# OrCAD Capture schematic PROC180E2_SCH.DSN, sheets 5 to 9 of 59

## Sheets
5 43. AUDIO MICROPHONE_LINE IN 2: size C; title: AUDIO - MICROPHONE/LINE IN 2
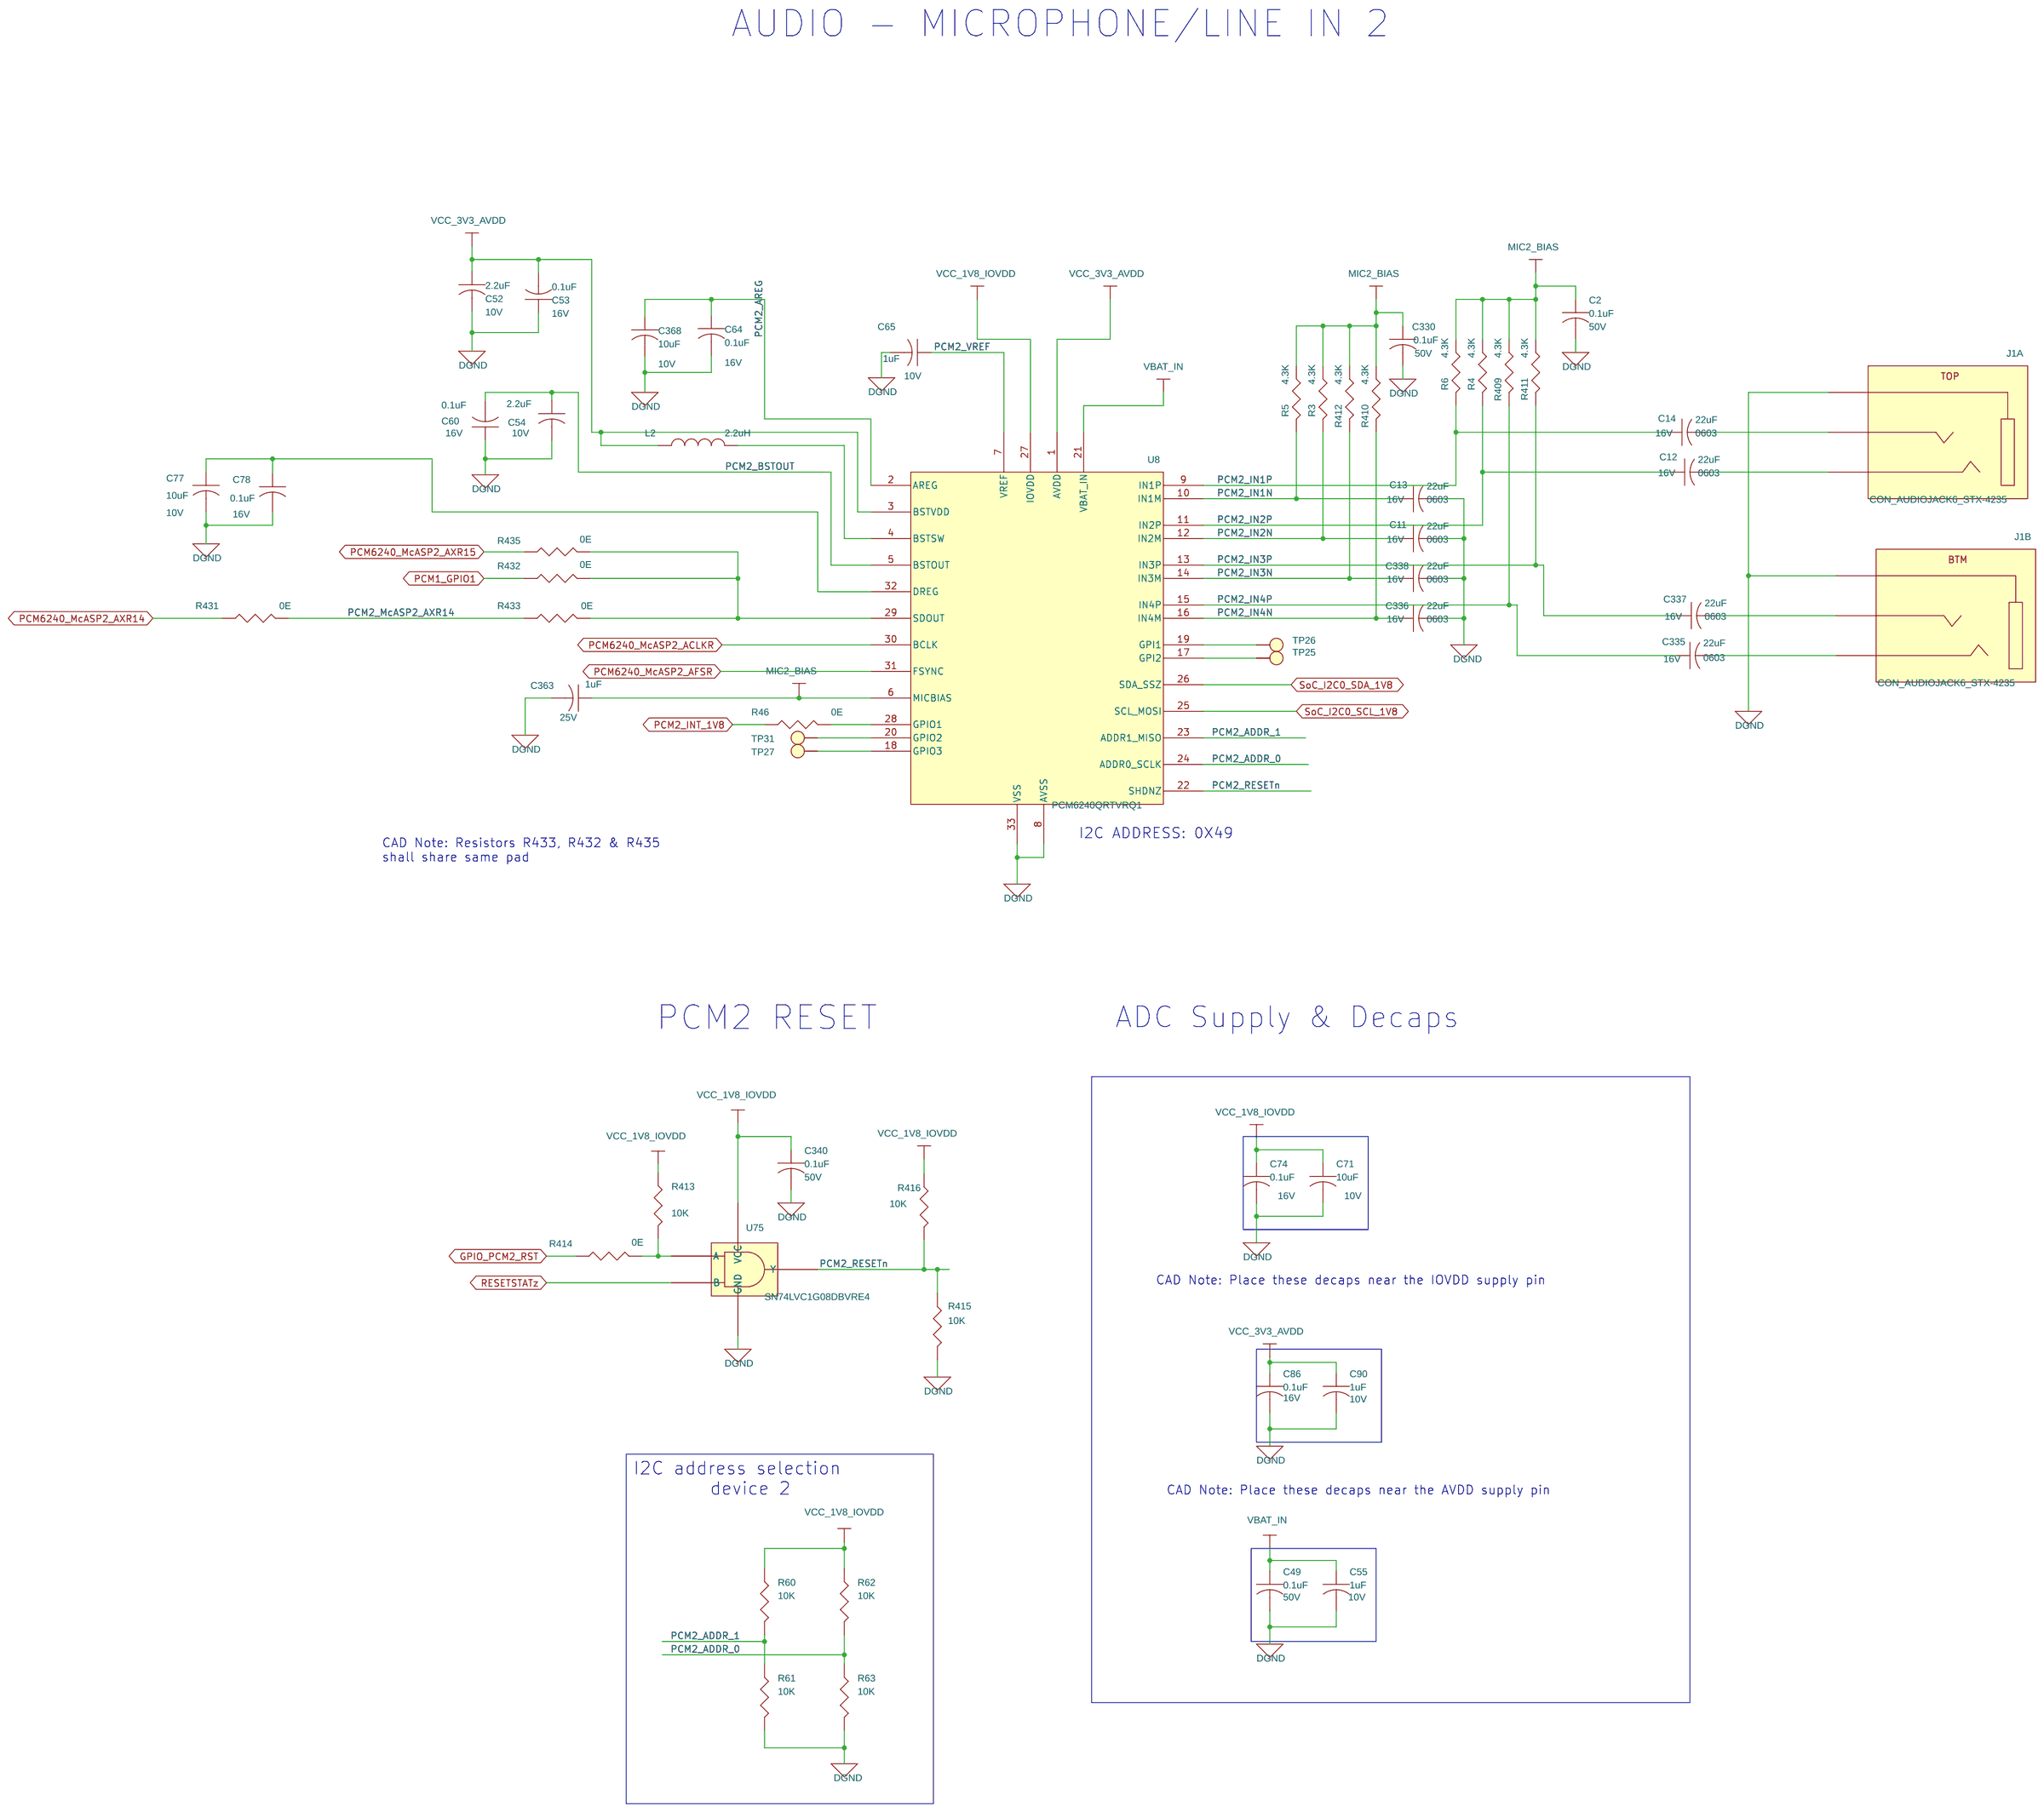
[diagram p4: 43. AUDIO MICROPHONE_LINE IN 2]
6 46. AUDIO EXPANSION 2: size C; title: AUDIO EXPANSION  CONNECTOR  #2
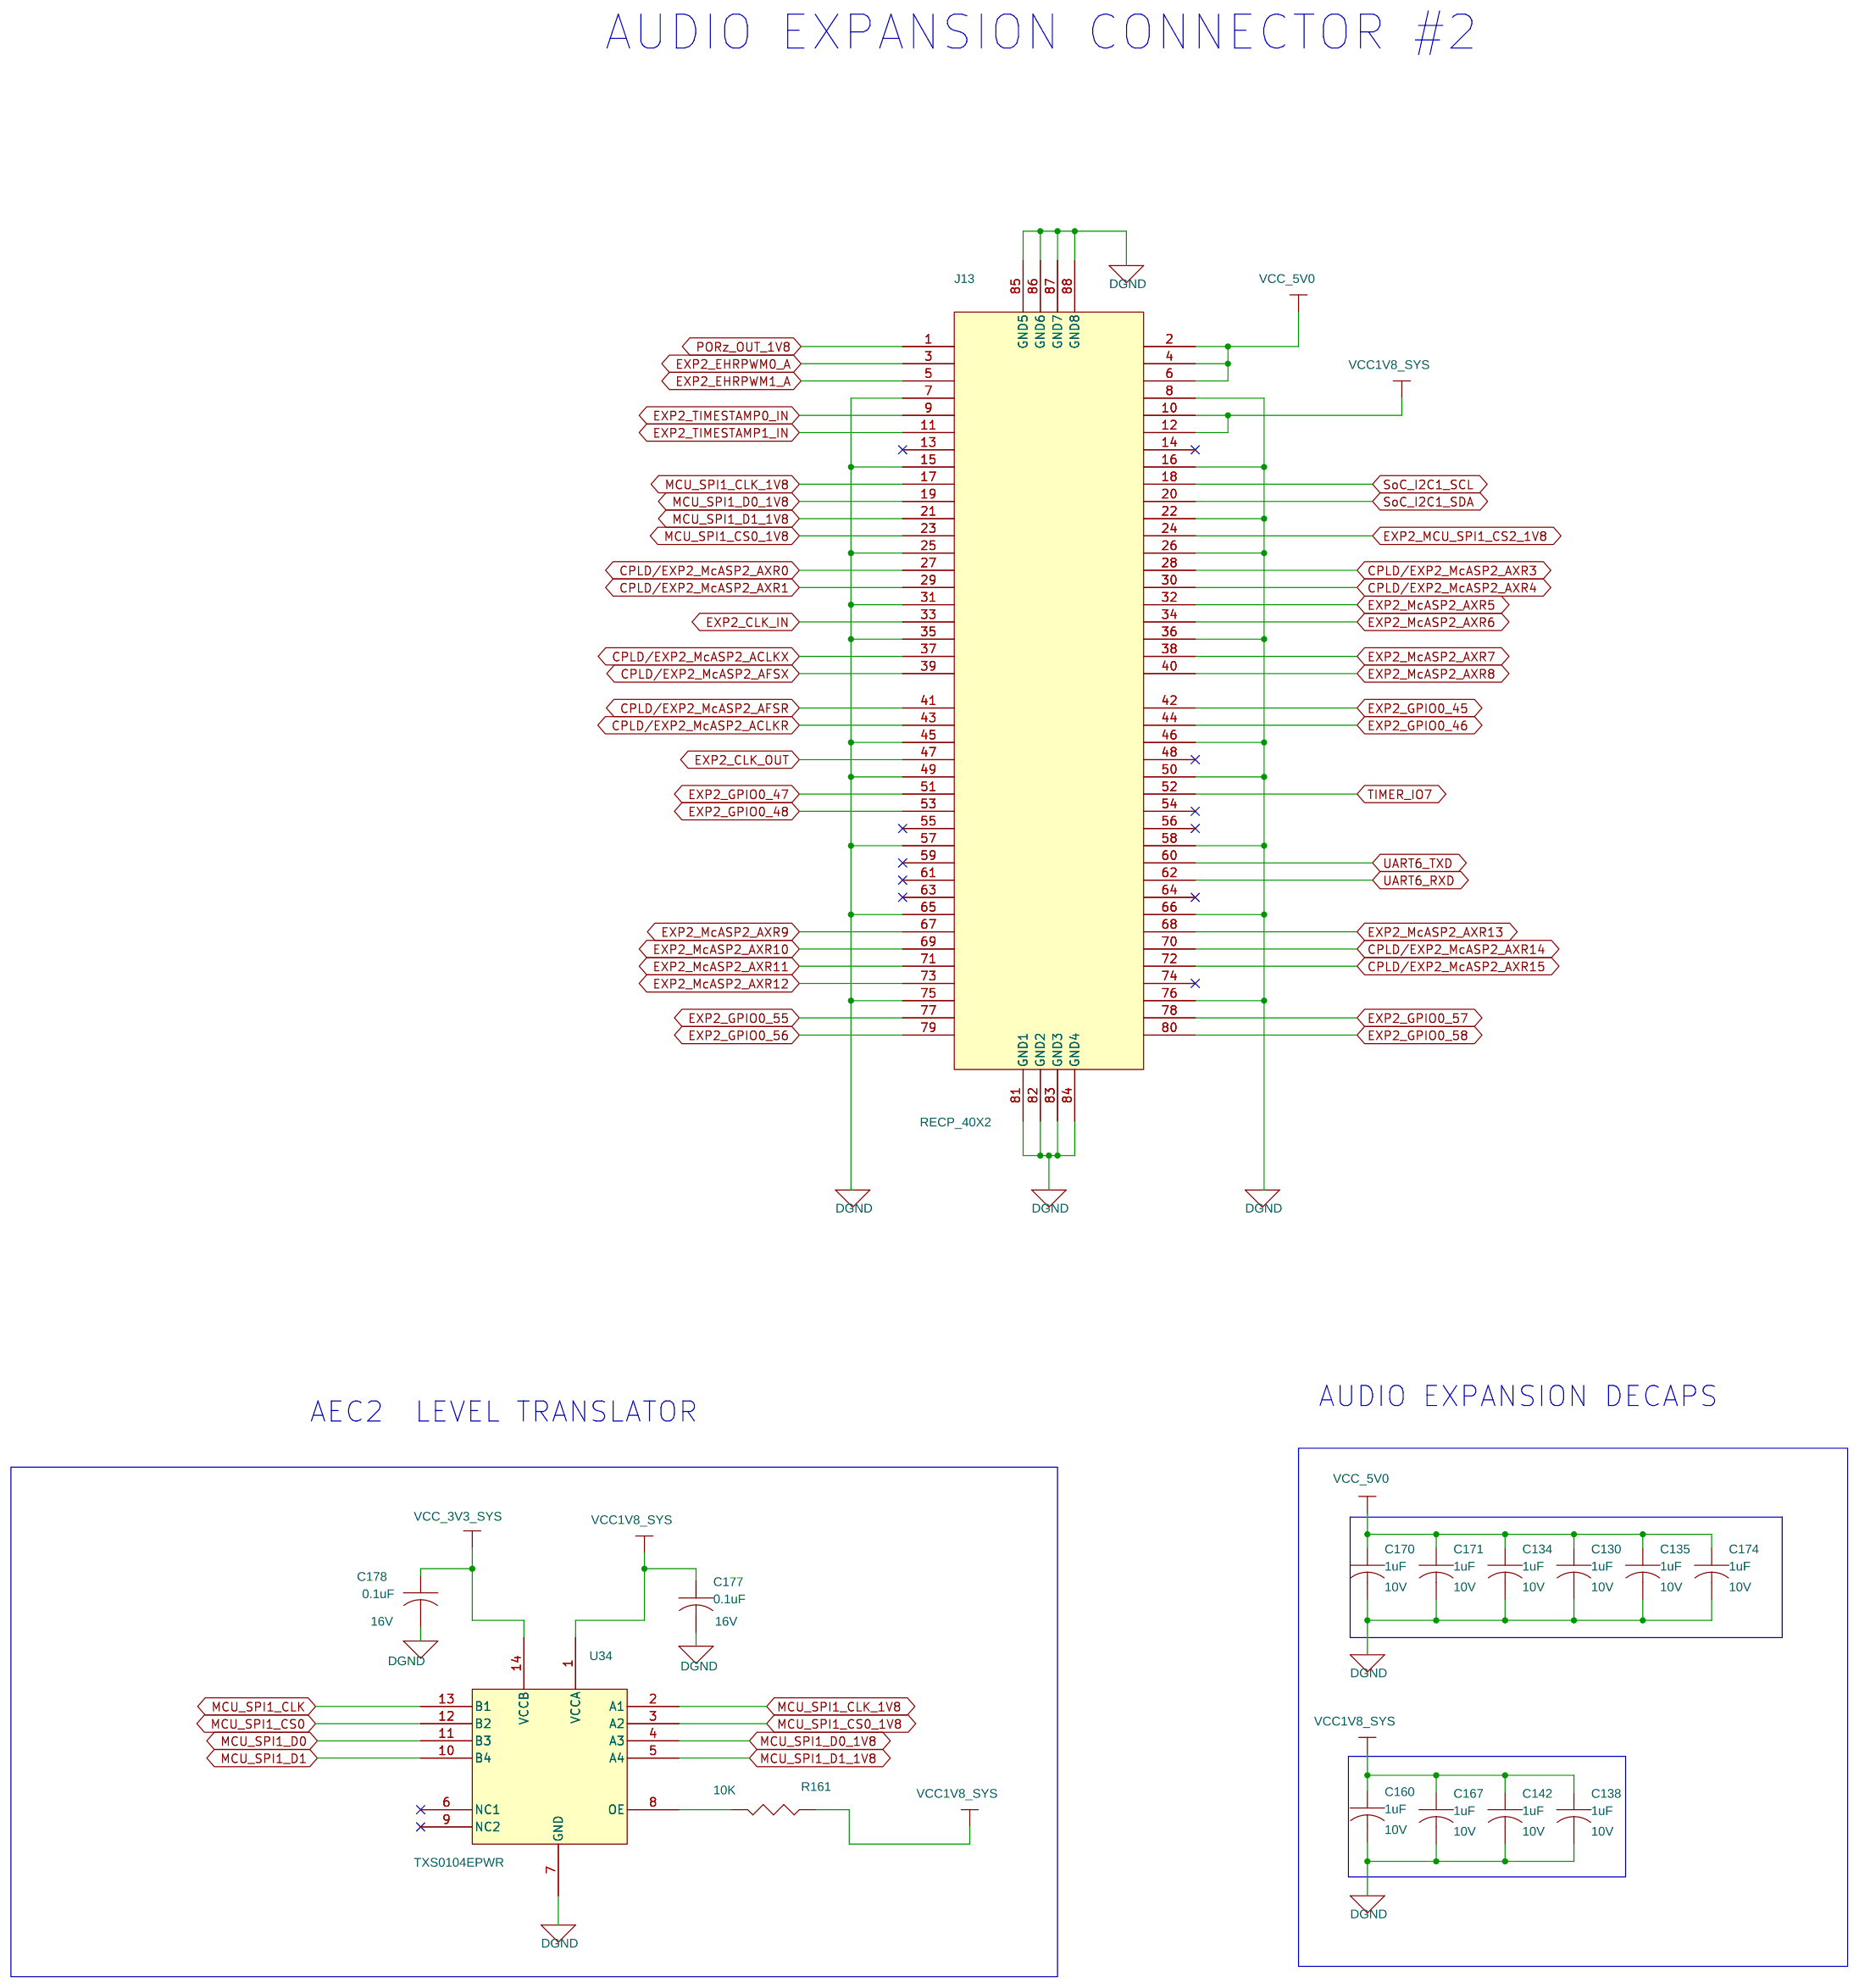
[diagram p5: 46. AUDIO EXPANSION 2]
7 30. SOC PERIPHERALS 3: size C; title: SOC PERIPHERALS 3
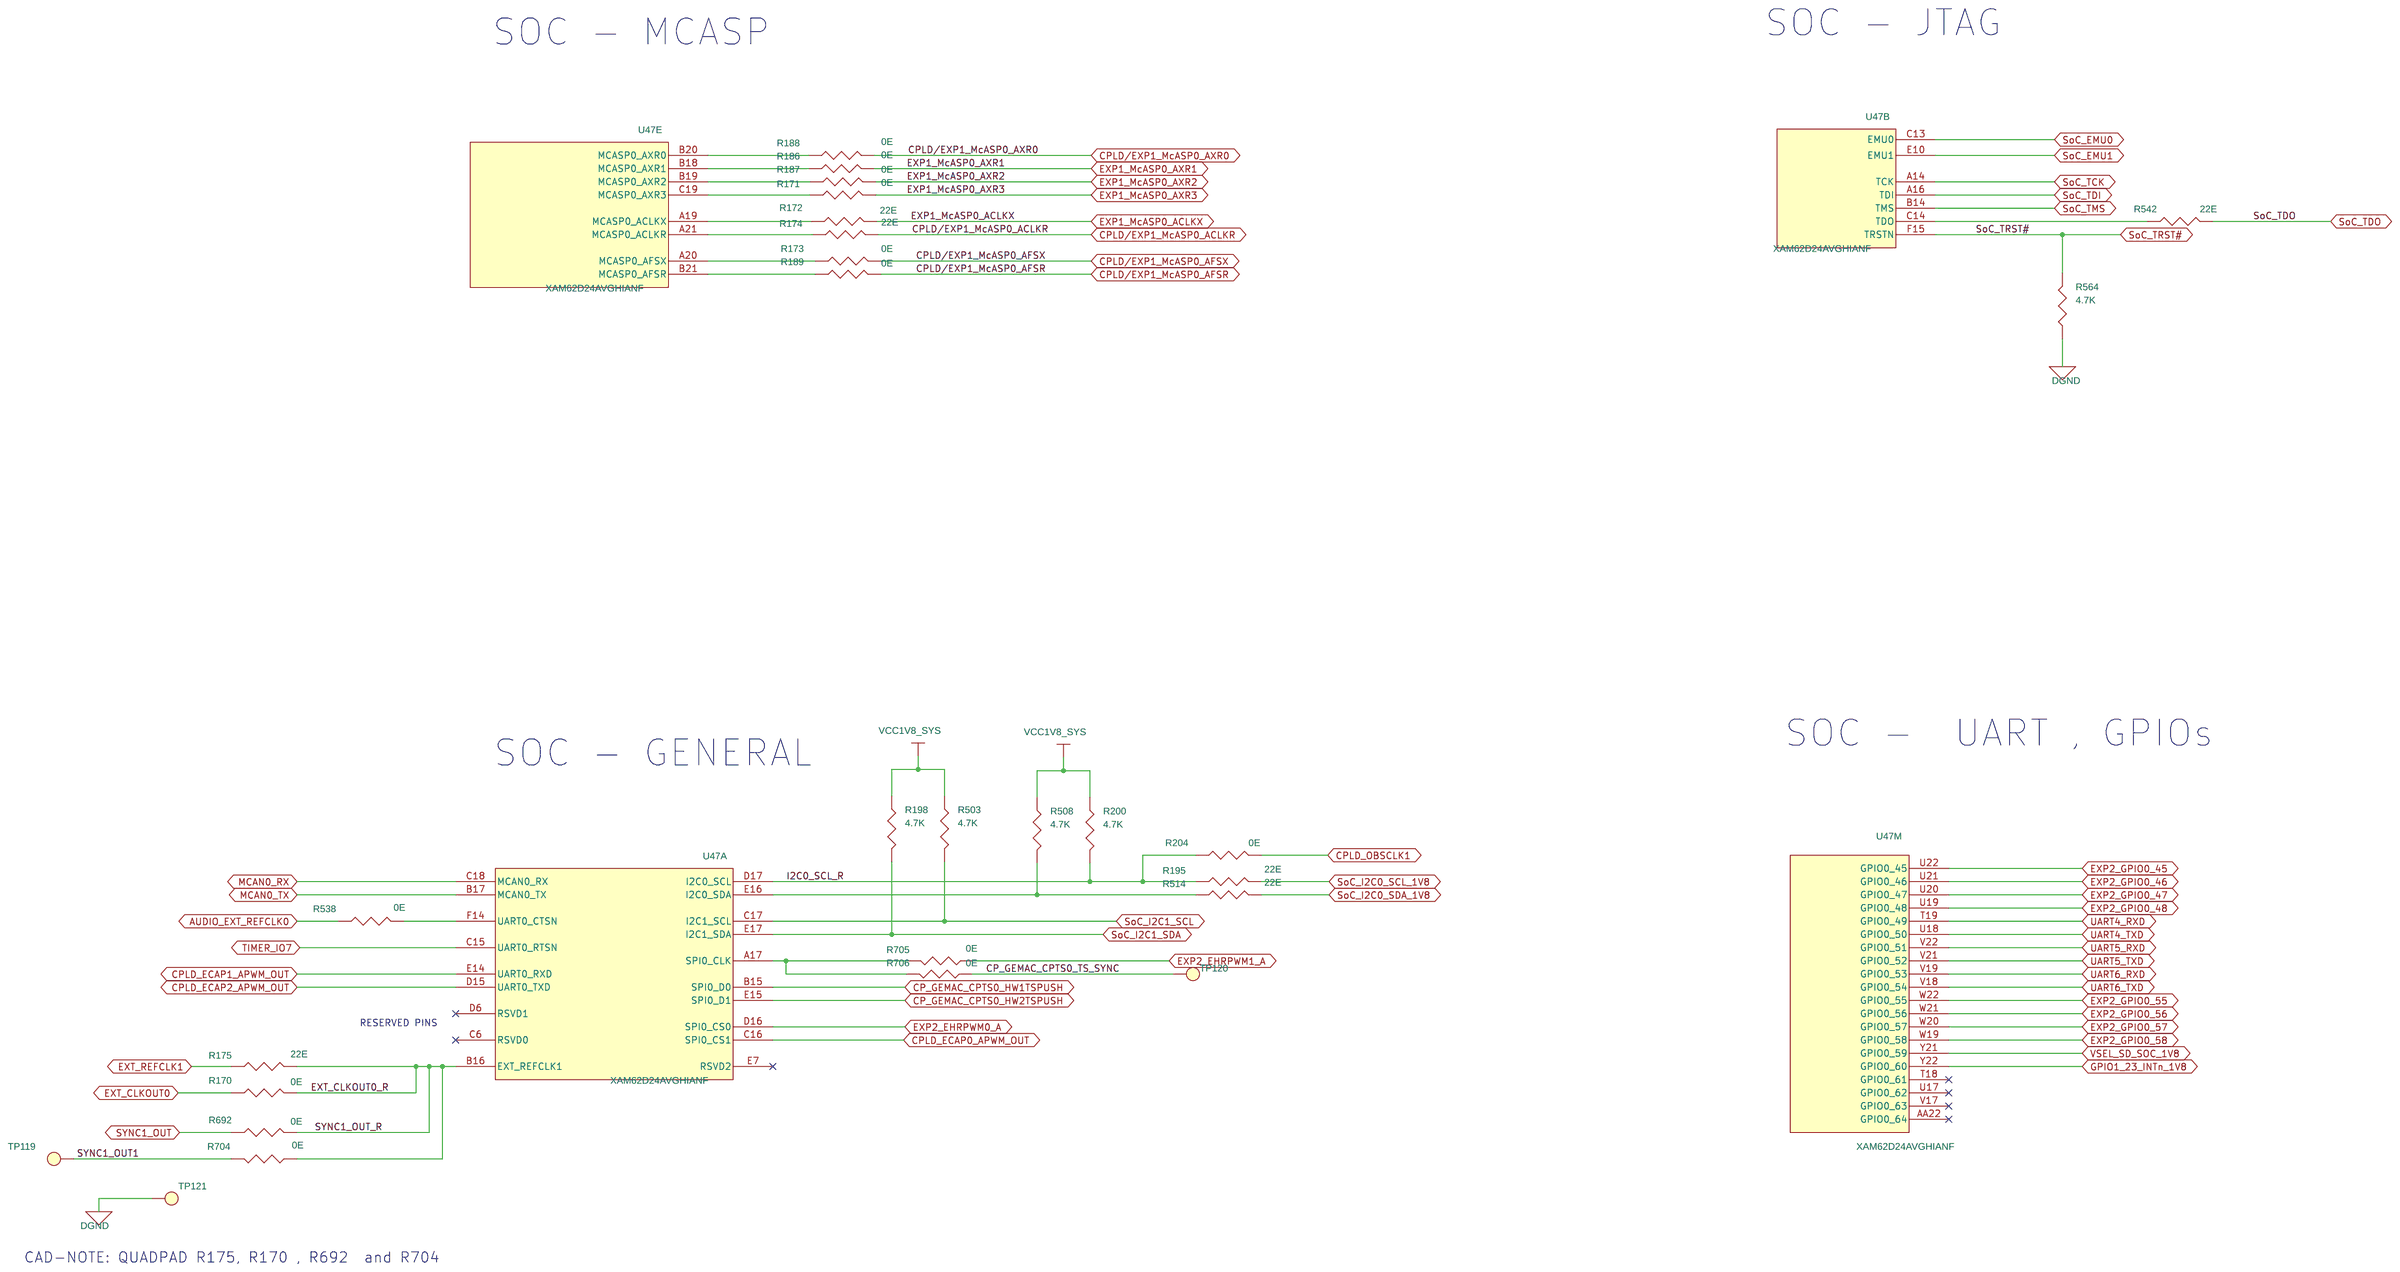
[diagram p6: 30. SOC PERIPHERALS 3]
8 29. SOC PERIPHERALS 2: size C; title: SOC PERIPHERALS  2
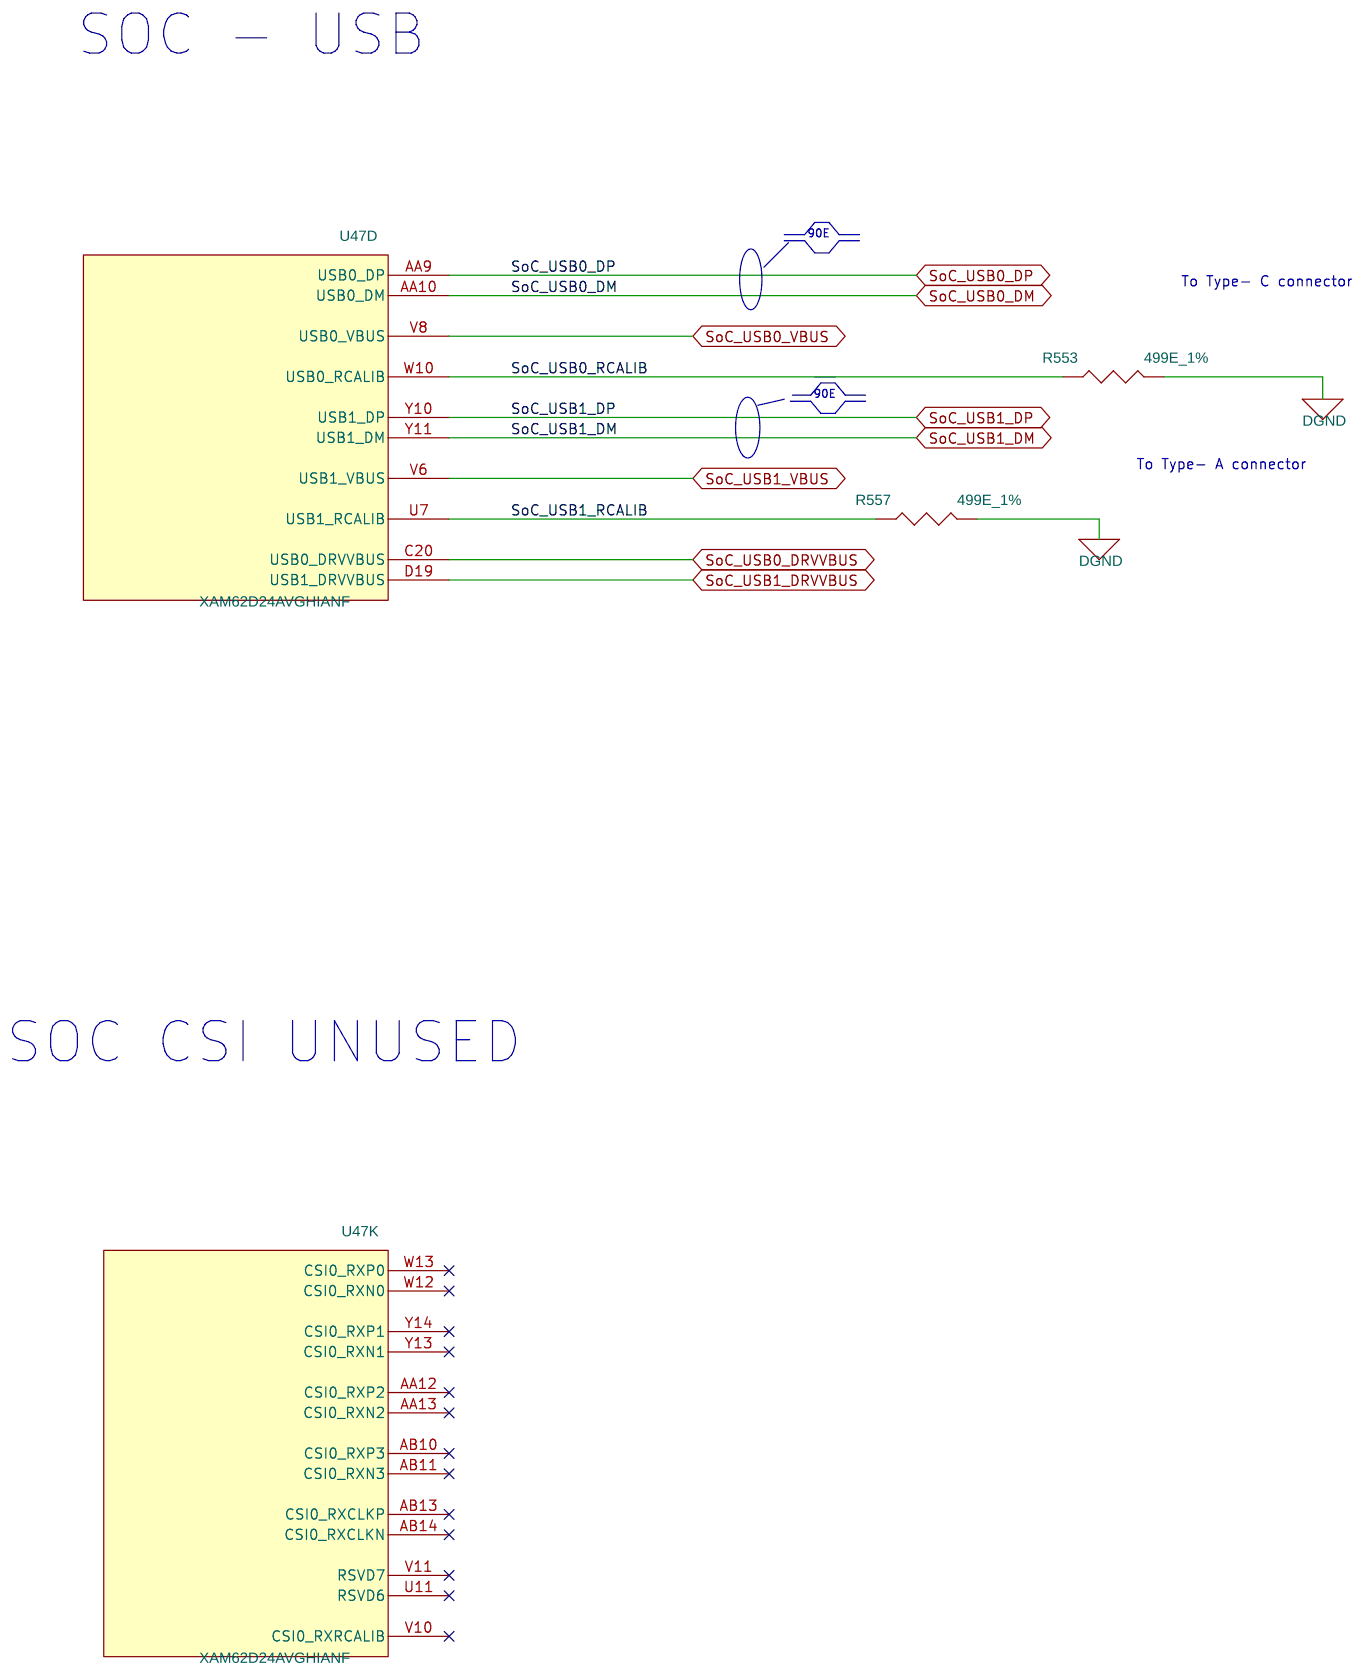
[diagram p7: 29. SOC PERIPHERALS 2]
9 23. BOOT MODE SWITCHES: size C; title: BOOT MODE SWITCHES
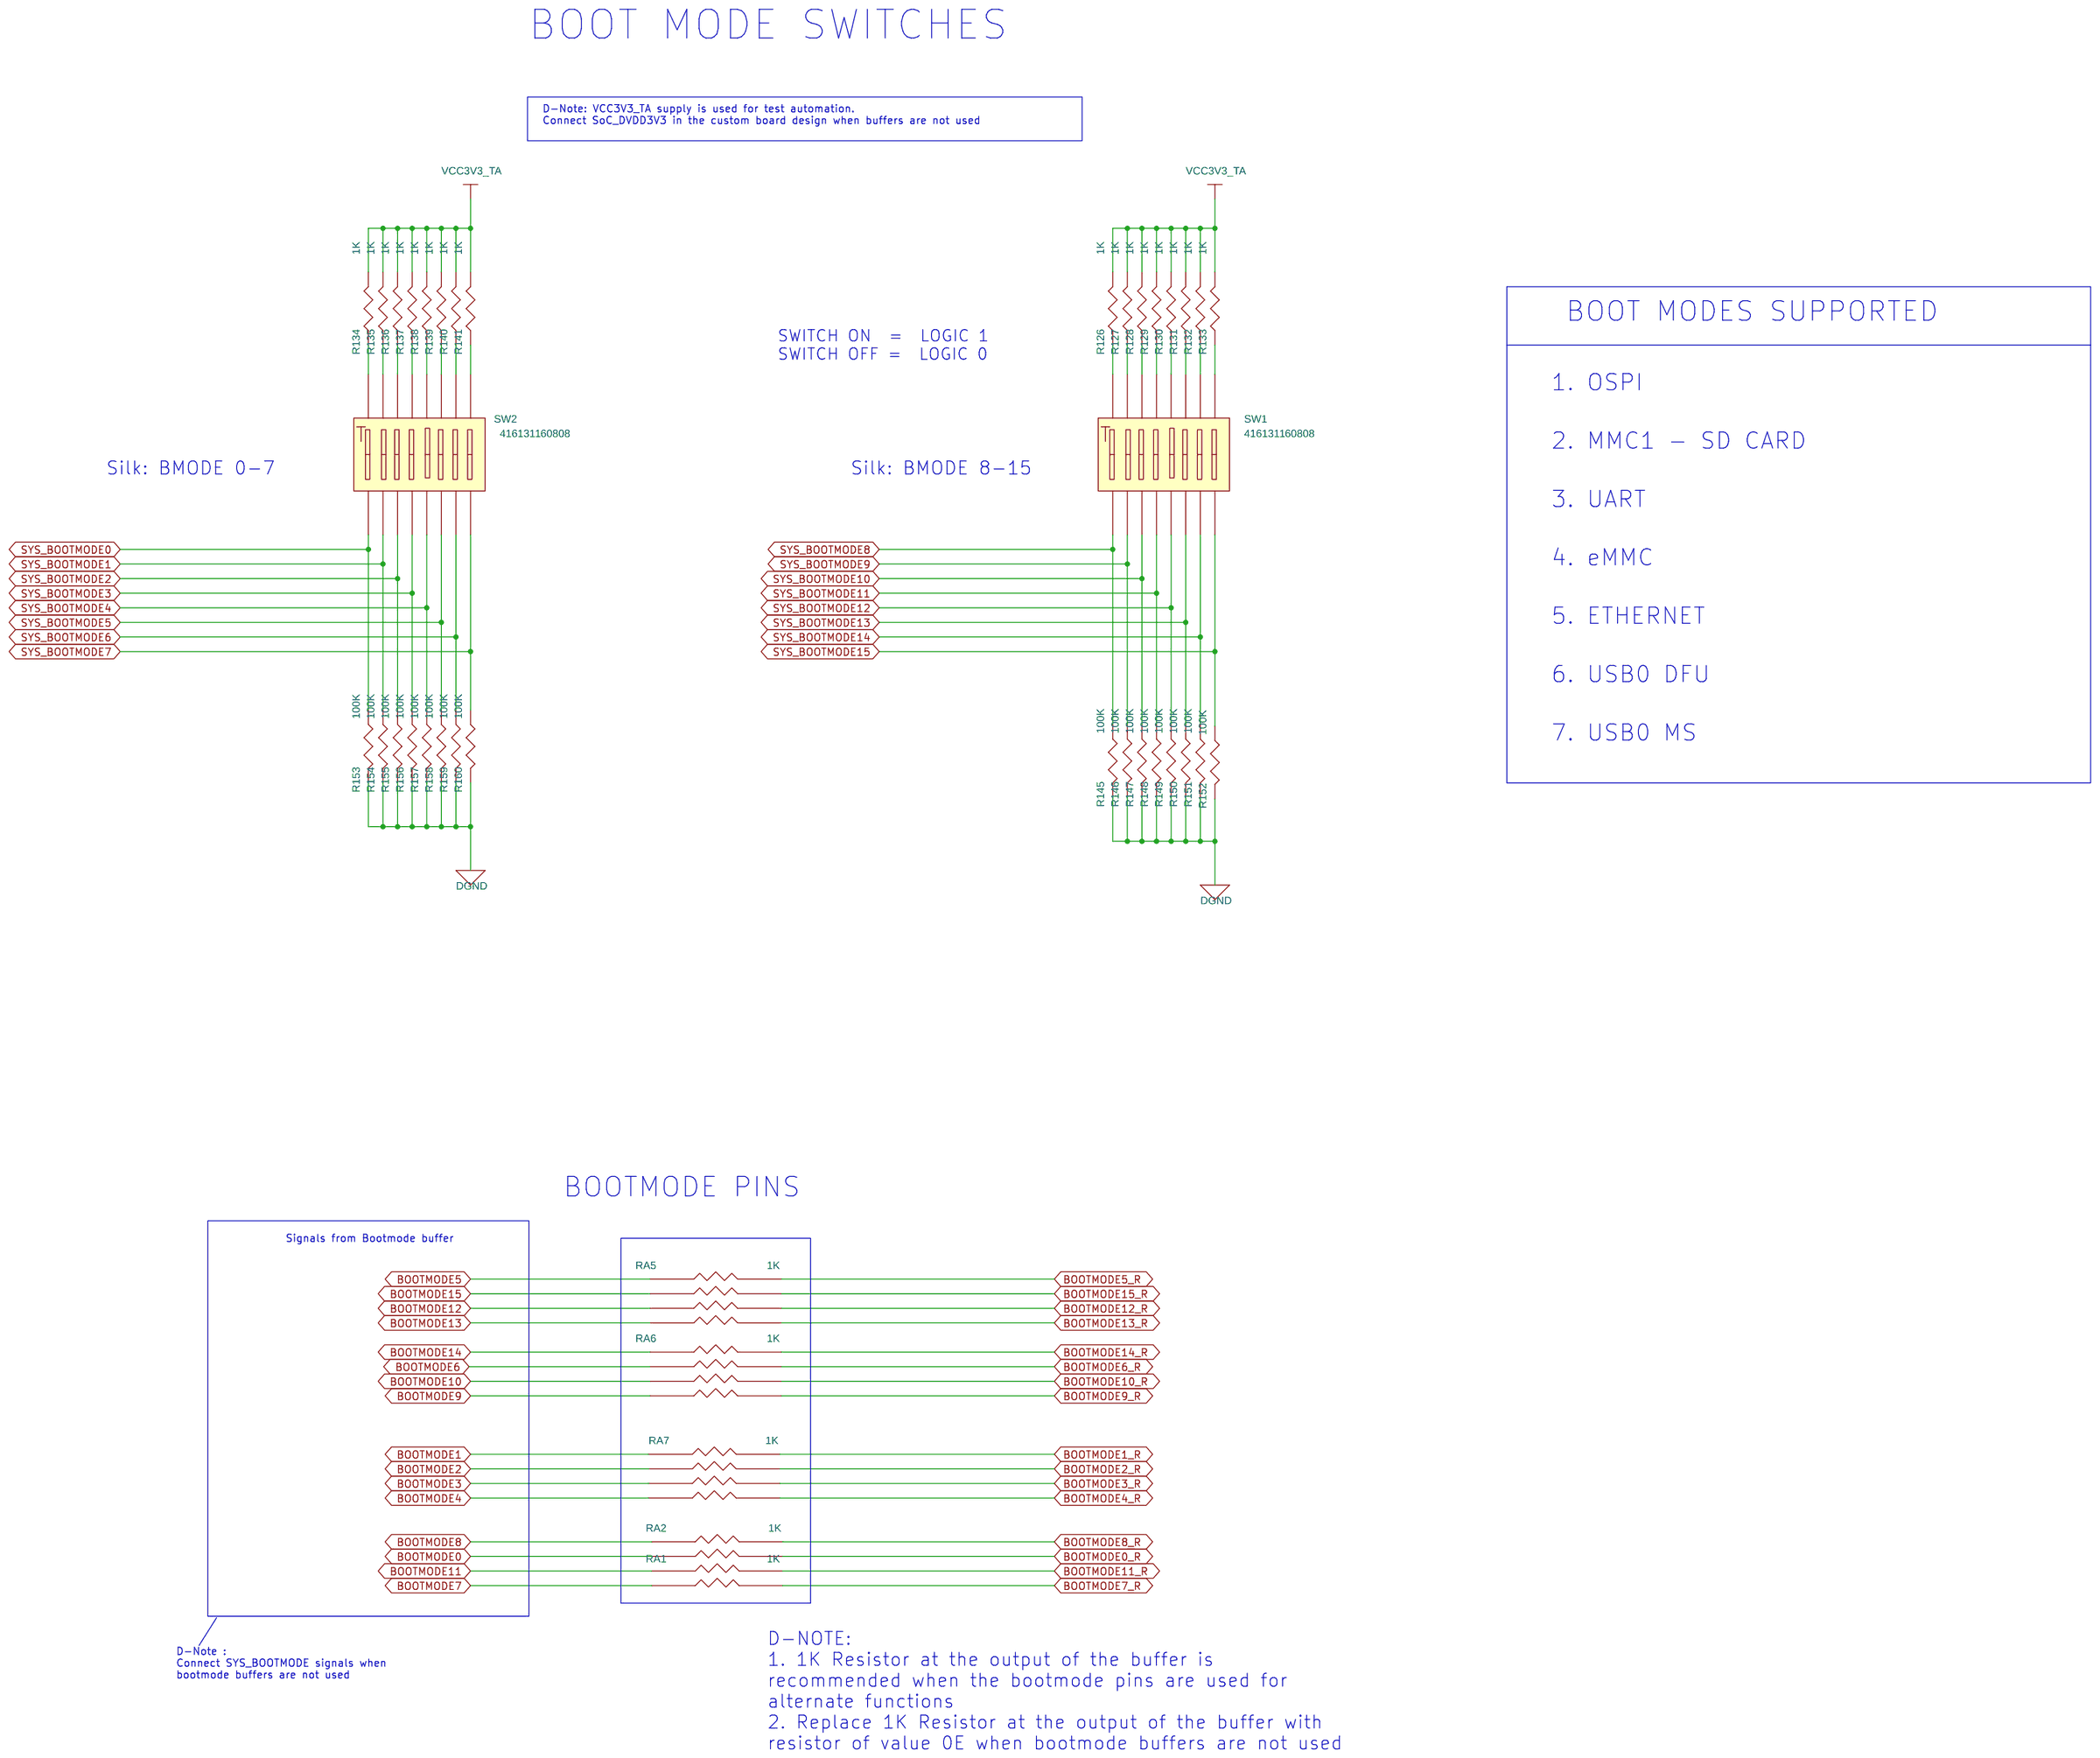
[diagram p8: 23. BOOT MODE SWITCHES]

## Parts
sheet 21. SOC RESET - 1
U47  XAM62D24AVGHIANF  [FBGA484_31-49_710X710_2-7]  (sections A,B,C,D,E,F,G,H,I,J,K,L,M,N,O,P,Q)
sheet 23. BOOT MODE SWITCHES
R126  1K  [RES0201_0-5]
R127  1K  [RES0201_0-5]
R128  1K  [RES0201_0-5]
R129  1K  [RES0201_0-5]
R130  1K  [RES0201_0-5]
R131  1K  [RES0201_0-5]
R132  1K  [RES0201_0-5]
R133  1K  [RES0201_0-5]
R134  1K  [RES0201_0-5]
R135  1K  [RES0201_0-5]
R136  1K  [RES0201_0-5]
R137  1K  [RES0201_0-5]
R138  1K  [RES0201_0-5]
R139  1K  [RES0201_0-5]
R140  1K  [RES0201_0-5]
R141  1K  [RES0201_0-5]
R145  100K  [RES0201_0-5]
R146  100K  [RES0201_0-5]
R147  100K  [RES0201_0-5]
R148  100K  [RES0201_0-5]
R149  100K  [RES0201_0-5]
R150  100K  [RES0201_0-5]
R151  100K  [RES0201_0-5]
R152  100K  [RES0201_0-5]
R153  100K  [RES0201_0-5]
R154  100K  [RES0201_0-5]
R155  100K  [RES0201_0-5]
R156  100K  [RES0201_0-5]
R157  100K  [RES0201_0-5]
R158  100K  [RES0201_0-5]
R159  100K  [RES0201_0-5]
R160  100K  [RES0201_0-5]
RA1  1K  [RESA_EXB_0201-2_0-5]
RA2  1K  [RESA_EXB_0201-2_0-5]
RA5  1K  [RESA_EXB_0201-4_0-5]
RA6  1K  [RESA_EXB_0201-4_0-5]
RA7  1K  [RESA_EXB_0201-4_0-5]
SW1  416131160808  [SW16_416131160808_460X230_SMD_2-7]
SW2  416131160808  [SW16_416131160808_460X230_SMD_2-7]
sheet 29. SOC PERIPHERALS 2
R553  499E_1%  [RES0402_0-5]
R557  499E_1%  [RES0402_0-5]
sheet 30. SOC PERIPHERALS 3
R170  0E  [RES0201_0-5]
R171  0E  [RES0402_0-5]
R172  22E  [RES0402_0-5]
R173  0E  [RES0402_0-5]
R174  22E  [RES0402_0-5]
R175  22E  [RES0201_0-5]
R186  0E  [RES0402_0-5]
R187  0E  [RES0402_0-5]
R188  0E  [RES0402_0-5]
R189  0E  [RES0402_0-5]
R195  22E  [RES0402_0-5]
R198  4.7K  [RES0201_0-5]
R200  4.7K  [RES0201_0-5]
R204  0E  [RES0201_0-5]
R503  4.7K  [RES0201_0-5]
R508  4.7K  [RES0201_0-5]
R514  22E  [RES0402_0-5]
R538  0E  [RES0201_0-5]
R542  22E  [RES0201_0-5]
R564  4.7K  [RES0201_0-5]
R692  0E  [RES0201_0-5]
R704  0E  [RES0201_0-5]
R705  0E  [RES0201_0-5]
R706  0E  [RES0201_0-5]
TP119  THRU HOLE  [TP_40X65]
TP120  THRU HOLE  [TP_40X65]
TP121  THRU HOLE  [TP_40X65]
sheet 43. AUDIO MICROPHONE_LINE IN 2
C2  0.1uF  [CAP0402_0-75]
C11  22uF  [CAP0603_1]
C12  22uF  [CAP0603_1]
C13  22uF  [CAP0603_1]
C14  22uF  [CAP0603_1]
C49  0.1uF  [CAP0402_0-75]
C52  2.2uF  [CAP0201_0-75]
C53  0.1uF  [CAP0201_0-5]
C54  2.2uF  [CAP0201_0-75]
C55  1uF  [CAP0201_0-5]
C60  0.1uF  [CAP0201_0-5]
C64  0.1uF  [CAP0201_0-5]
C65  1uF  [CAP0201_0-5]
C71  10uF  [CAP0402_0-75]
C74  0.1uF  [CAP0201_0-5]
C77  10uF  [CAP0402_0-75]
C78  0.1uF  [CAP0201_0-5]
C86  0.1uF  [CAP0201_0-5]
C90  1uF  [CAP0201_0-5]
C330  0.1uF  [CAP0402_0-75]
C335  22uF  [CAP0603_1]
C336  22uF  [CAP0603_1]
C337  22uF  [CAP0603_1]
C338  22uF  [CAP0603_1]
C340  0.1uF  [CAP0402_0-75]
C363  1uF  [CAP0805_1-5]
C368  10uF  [CAP0402_0-75]
J1  CON_AUDIOJACK6_STX-4235  [CON_AV6_STX-4235-3-3_S_R_T_26]  (sections A,B)
L2  2.2uH  [IND0806]
R3  4.3K  [RES0402_0-5]
R4  4.3K  [RES0402_0-5]
R5  4.3K  [RES0402_0-5]
R6  4.3K  [RES0402_0-5]
R46  0E  [RES0201_0-5]
R60  10K  [RES0201_0-5]
R61  10K  [RES0201_0-5]
R62  10K  [RES0201_0-5]
R63  10K  [RES0201_0-5]
R409  4.3K  [RES0402_0-5]
R410  4.3K  [RES0402_0-5]
R411  4.3K  [RES0402_0-5]
R412  4.3K  [RES0402_0-5]
R413  10K  [RES0402_0-5]
R414  0E  [RES0201_0-5]
R415  10K  [RES0402_0-5]
R416  10K  [RES0402_0-5]
R431  0E  [RES0201_0-5]
R432  0E  [RES0201_0-5]
R433  0E  [RES0201_0-5]
R435  0E  [RES0201_0-5]
TP25  TP30_SMD  [TP30_SMD]
TP26  TP30_SMD  [TP30_SMD]
TP27  TP30_SMD  [TP30_SMD]
TP31  TP30_SMD  [TP30_SMD]
U8  PCM6240QRTVRQ1  [QFN32_19-68_200X200_0-8_EP3-6]
U75  SN74LVC1G08DBVRE4  [SOT23-5]
sheet 46. AUDIO EXPANSION 2
C130  1uF  [CAP0201_0-5]
C134  1uF  [CAP0201_0-5]
C135  1uF  [CAP0201_0-5]
C138  1uF  [CAP0201_0-5]
C142  1uF  [CAP0201_0-5]
C160  1uF  [CAP0201_0-5]
C167  1uF  [CAP0201_0-5]
C170  1uF  [CAP0201_0-5]
C171  1uF  [CAP0201_0-5]
C174  1uF  [CAP0201_0-5]
C177  0.1uF  [CAP0201_0-5]
C178  0.1uF  [CAP0201_0-5]
J13  RECP_40X2  [CON_40X2_QSE-040-01_S_S_S]
R161  10K  [RES0201_0-5]
U34  TXS0104EPWR  [TSSOP14_25-59_205X180_1-2]

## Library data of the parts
U47 = AM62D_EVM_SOC_FCBGA484: IC AM62D EVM SoC MICROPROCESSOR FCBGA484; Chkd/date: PRADEEP/010424; Crtd /date: PRADEEP/010424; Custom_Duty: 15%; Customs_HS_Code: 85423100; Distributor_name: NA; Distributor_part_number: NA; Footprint Path: Y:\MIS_DATABASE\Library\ALTIUM_TOOL\PCB_FOOTPRINTS\Altium_Footprint_Lib.PcbLib; Height: 2.65MM; Library Ref: AM62D_EVM_SoC_FCBGA484; Mfr_name: TEXAS INSTRUMENTS; Mistral Part No: 141224040001-R; Package: FCBGA484; Part_type: ICS\DIGITAL\MICROPROCESSOR; Project: AM62D_EVM; RoHS: NA; Temperature: NA; Tolerance: NA; Voltage: NA; Wattage: NA; Weight: NA; Datasheet: Y:\MIS_DATABASE\DATASHEETS\ICS\DIGITAL\MICROCONTROLLER\AM62A_SK_EVM.PDF
R126-R141 = RESISTOR: RES 1K 1/20W 5% 0201; Chkd/date: MANIRAJA/050517; Crtd /date: MANIRAJA/050517; Custom_Duty: 15%; Customs_HS_Code: 85332119; Distributor_name: DIGIKEY; Distributor_part_number: 311-1KNCT-ND; Footprint Path: Y:\MIS_DATABASE\Library\ALTIUM_TOOL\PCB_FOOTPRINTS\Altium_Footprint_Lib.PcbLib; Height: 0.26MM; Library Path: Y:\MIS_DATABASE\Library\ALTIUM_TOOL\SCHEMATICS_PARTS\MS_DISCRETE_Library.schlib; Mfr_name: YAGEO AMERICA; Mfr_part_number: RC0201JR-071KL; Mistral Part No: 110009030395-R; Package: 0201; Part_type: RESISTORS\FIXED; Project: GOLDEN-I LITE; RoHS: RoHS; Temperature: -55°C+125°C; Tolerance: 5%; Voltage: NA; Wattage: 1/20W; Weight: 0.17mg; Datasheet: Y:\MIS_DATABASE\DATASHEETS\RESISTORS\RCXXXXL-SER_MAR18.PDF
R145-R160 = RESISTOR: RES 100K 1/20W 5% 0201; Chkd/date: MANIRAJA/050517; Crtd /date: MANIRAJA/050517; Custom_Duty: 15%; Customs_HS_Code: 85332119; Distributor_name: DIGIKEY; Distributor_part_number: 311-100KNCT-ND; Footprint Path: Y:\MIS_DATABASE\Library\ALTIUM_TOOL\PCB_FOOTPRINTS\Altium_Footprint_Lib.PcbLib; Height: 0.26MM; Library Path: Y:\MIS_DATABASE\Library\ALTIUM_TOOL\SCHEMATICS_PARTS\MS_DISCRETE_Library.schlib; Mfr_name: YAGEO AMERICA; Mfr_part_number: RC0201JR-07100KL; Mistral Part No: 110009030176-R; Package: 0201; Part_type: RESISTORS\FIXED; Project: GOLDEN-I LITE; RoHS: RoHS; Temperature: -55°C+125°C; Tolerance: 5%; Voltage: NA; Wattage: 1/20W; Weight: 0.17mg; Datasheet: Y:\MIS_DATABASE\DATASHEETS\RESISTORS\RCXXXXL-SER_MAR18.PDF
RA1 RA2 = RESARR_ISO2: RES ARRAY 1K 5% 0201-2; Chkd/date: TAMILARASU/110424; Crtd /date: TAMILARASU/110424; Custom_Duty: 15%; Customs_HS_Code: 85332119; Distributor_name: DIGIKEY; Distributor_part_number: 10-EXB-U14102JXTR-ND; Footprint Path: Y:\MIS_DATABASE\Library\ALTIUM_TOOL\PCB_FOOTPRINTS\Altium_Footprint_Lib.PcbLib; Height: 0.45MM; Library Path: Y:\MIS_DATABASE\Library\ALTIUM_TOOL\SCHEMATICS_PARTS\MS_DISCRETE_Library.schlib; Mfr_name: PANASONIC-ECG; Mfr_part_number: EXB-U14102JX; Mistral Part No: 110024040002-R; Package: 0201-2; Part_type: RESISTORS\ARRAY; Project: AM62D_EVM; RoHS: RoHS; Temperature: -55°C+125°C; Tolerance: 5%; Voltage: NA; Wattage: 31mW; Weight: NA; Datasheet: Y:\MIS_DATABASE\DATASHEETS\RESISTORS\EXB-U14.PDF
RA5-RA7 = RESARR_ISO4: RES ARRAY 1K 31mW 5% 0201-4; Chkd/date: NAVEED/110515; Crtd /date: VASANTHA/080515; Custom_Duty: 15%; Customs_HS_Code: 85332119; Distributor_name: DIGIKEY; Distributor_part_number: Y6102CT-ND; Footprint Path: Y:\MIS_DATABASE\Library\ALTIUM_TOOL\PCB_FOOTPRINTS\Altium_Footprint_Lib.PcbLib; Height: 0.45MM; Library Path: Y:\MIS_DATABASE\Library\ALTIUM_TOOL\SCHEMATICS_PARTS\MS_DISCRETE_Library.schlib; Mfr_name: PANASONIC-ECG; Mfr_part_number: EXB-18V102JX; Mistral Part No: 110015050003-R; Package: 0201-4; Part_type: RESISTORS\ARRAY; Project: FREE SCALE NANO; RoHS: RoHS; Temperature: -55°C+125°C; Tolerance: 5%; Voltage: NA; Wattage: 31mW; Weight: 1mg; Datasheet: Y:\MIS_DATABASE\DATASHEETS\RESISTORS\EXB-18V.PDF
SW1 SW2 = SW16_CHS-08A: SWITCH SLIDE SPST ST SMD; Chkd/date: MANIRAJA/051020; Crtd /date: ALVY/011020; Custom_Duty: 24%; Customs_HS_Code: 85369090; Distributor_name: DIGIKEY; Distributor_part_number: 732-3857-1-ND; Footprint Path: Y:\MIS_DATABASE\Library\ALTIUM_TOOL\PCB_FOOTPRINTS\Altium_Footprint_Lib.PcbLib; Height: 2.65MM; Library Path: Y:\MIS_DATABASE\Library\ALTIUM_TOOL\SCHEMATICS_PARTS\MS_SWITCH_Library.schlib; Mfr_name: WURTH ELECTRONICS; Mistral Part No: 130020100001-R; Package: SMD; Part_type: ELECTRO-MECHANICAL\SWITCH; Project: AM64X_SKEVM; RoHS: RoHS; Temperature: -40°C+85°C; Tolerance: NA; Voltage: NA; Wattage: NA; Weight: 281.7mg; Datasheet: Y:\MIS_DATABASE\DATASHEETS\MISC\SWITCHES\4161311608XX.PDF
R553 R557 = RESISTOR: RES 499E 1/16W 1% 0402; Chkd/date: MANIRAJA/051020; Crtd /date: ALVY/051020; Custom_Duty: 15%; Customs_HS_Code: 85332119; Distributor_name: DIGIKEY; Distributor_part_number: 311-499LRCT-ND; Footprint Path: Y:\MIS_DATABASE\Library\ALTIUM_TOOL\PCB_FOOTPRINTS\Altium_Footprint_Lib.PcbLib; Height: 0.40MM; Library Path: Y:\MIS_DATABASE\Library\ALTIUM_TOOL\SCHEMATICS_PARTS\MS_DISCRETE_Library.schlib; Mfr_name: YAGEO AMERICA; Mfr_part_number: RC0402FR-07499RL; Mistral Part No: 110020080006-R; Package: 0402; Part_type: RESISTORS\FIXED; Project: AM64XX_EVM; RoHS: RoHS; Temperature: -55°C+155°C; Tolerance: 1%; Voltage: NA; Wattage: 1/16W; Weight: 0.65mg; Datasheet: Y:\MIS_DATABASE\DATASHEETS\RESISTORS\RCXXXXL-SER_MAR18.PDF
R46 R170 R204 R414 R431-R433 R435 R692 R704-R706 = RESISTOR: RES 0E 1/20W 5% 0201; Chkd/date: NAVEED/301214; Crtd /date: MUDDU/120710; Custom_Duty: 15%; Customs_HS_Code: 85332119; Distributor_name: DIGIKEY; Distributor_part_number: 311-0.0NCT-ND; Footprint Path: Y:\MIS_DATABASE\Library\ALTIUM_TOOL\PCB_FOOTPRINTS\Altium_Footprint_Lib.PcbLib; Height: 0.26MM; Library Path: Y:\MIS_DATABASE\Library\ALTIUM_TOOL\SCHEMATICS_PARTS\MS_DISCRETE_Library.schlib; Mfr_name: YAGEO AMERICA; Mfr_part_number: RC0201JR-070RL; Mistral Part No: 110010070067-R; Package: 0201; Part_type: RESISTORS\FIXED; Project: PB_BUGBASE; RoHS: RoHS; Temperature: -55°C+125°C; Tolerance: 5%; Voltage: NA; Wattage: 1/20W; Weight: 0.17mg; Datasheet: Y:\MIS_DATABASE\DATASHEETS\RESISTORS\RCXXXXL-SER_MAR18.PDF
R171 R173 R186-R189 = RESISTOR: RES 0E 1/10W JUMPER 0402; Chkd/date: VASANTHA/061216; Crtd /date: NAVEED/201014; Custom_Duty: 15%; Customs_HS_Code: 85332119; Distributor_name: DIGIKEY; Distributor_part_number: P0.0JCT-ND; Footprint Path: Y:\MIS_DATABASE\Library\ALTIUM_TOOL\PCB_FOOTPRINTS\Altium_Footprint_Lib.PcbLib; Height: 0.40MM; IBISSP_MODLES: VALUE REPEATING 2 TIME; Library Path: Y:\MIS_DATABASE\Library\ALTIUM_TOOL\SCHEMATICS_PARTS\MS_DISCRETE_Library.schlib; Mfr_name: PANASONIC-ECG; Mfr_part_number: ERJ-2GE0R00X; Mistral Part No: 110018030052-R; Package: 0402; Part_type: RESISTORS\FIXED; Project: AEGIS POM; RoHS: RoHS; Temperature: -55°C+155°C; Tolerance: NA; Voltage: NA; Wattage: 1/10W; Weight: 0.8mg; Datasheet: Y:\MIS_DATABASE\DATASHEETS\RESISTORS\PAN-ERJSER_NOV17.PDF
R172 R174 R195 R514 = RESISTOR: RES 22E 1/10W 5% 0402; Chkd/date: VASANTHA/060117; Crtd /date: MAZHAR/120505; Custom_Duty: 15%; Customs_HS_Code: 85332119; Distributor_name: DIGIKEY; Distributor_part_number: P22JCT-ND; Footprint Path: Y:\MIS_DATABASE\Library\ALTIUM_TOOL\PCB_FOOTPRINTS\Altium_Footprint_Lib.PcbLib; Height: 0.40MM; Library Path: Y:\MIS_DATABASE\Library\ALTIUM_TOOL\SCHEMATICS_PARTS\MS_DISCRETE_Library.schlib; Mfr_name: PANASONIC-ECG; Mfr_part_number: ERJ-2GEJ220X; Mistral Part No: 110009030515-R; Package: 0402; Part_type: RESISTORS\FIXED; Project: EPDA_CORE; RoHS: RoHS; Temperature: -55°C+155°C; Tolerance: 5%; Voltage: NA; Wattage: 1/10W; Weight: 0.8mg; Datasheet: Y:\MIS_DATABASE\DATASHEETS\RESISTORS\PAN-ERJSER_NOV17.PDF
R175 R542 = RESISTOR: RES 22E 1/20W 5% 0201; Chkd/date: ALVY/210122; Crtd /date: TAMILARASU/210122; Custom_Duty: 15%; Customs_HS_Code: 85332119; Distributor_name: DIGIKEY; Distributor_part_number: 541-22AGCT-ND; Footprint Path: Y:\MIS_DATABASE\Library\ALTIUM_TOOL\PCB_FOOTPRINTS\Altium_Footprint_Lib.PcbLib; Height: 0.28MM; Library Path: Y:\MIS_DATABASE\Library\ALTIUM_TOOL\SCHEMATICS_PARTS\MS_DISCRETE_Library.schlib; Mfr_name: VISHAY; Mfr_part_number: CRCW020122R0JNED; Mistral Part No: 110022010021-R; Package: 0201; Part_type: RESISTORS\FIXED; Project: DLRL DIGITAL RECEIVER_BRD; RoHS: RoHS; Temperature: -55°C+155°C; Tolerance: 5%; Voltage: NA; Wattage: 1/20W; Weight: 0.17mg; Datasheet: Y:\MIS_DATABASE\DATASHEETS\RESISTORS\CRCW0201.PDF
R198 R200 R503 R508 R564 = RESISTOR: RES 4.7K 1/20W 5% 0201; Chkd/date: MANIRAJA/200921; Crtd /date: ALVY/200921; Custom_Duty: 15%; Customs_HS_Code: 85332119; Distributor_name: DIGIKEY; Distributor_part_number: 311-4.7KNCT-ND; Footprint Path: Y:\MIS_DATABASE\Library\ALTIUM_TOOL\PCB_FOOTPRINTS\Altium_Footprint_Lib.PcbLib; Height: 0.26MM; Library Path: Y:\MIS_DATABASE\Library\ALTIUM_TOOL\SCHEMATICS_PARTS\MS_DISCRETE_Library.schlib; Mfr_name: YAGEO AMERICA; Mfr_part_number: RC0201JR-074K7L; Mistral Part No: 110021090007-R; Package: 0201; Part_type: RESISTORS\FIXED; Project: TI_AM62x SKEVM_BRD; RoHS: RoHS; Temperature: -55°C+125°C; Tolerance: 5%; Voltage: NA; Wattage: 1/20W; Weight: 0.17mg; Datasheet: Y:\MIS_DATABASE\DATASHEETS\RESISTORS\RCXXXXL-SER_MAR18.PDF
R538 = RESISTOR: RES 0E 1/20W 5% 0201; Chkd/date: NAVEED/301214; Crtd /date: MUDDU/120710; Custom_Duty: 15%; Customs_HS_Code: 85332119; Distributor_name: DIGIKEY; Distributor_part_number: 311-0.0NCT-ND; Footprint Path: Y:\MIS_DATABASE\Library\ALTIUM_TOOL\PCB_FOOTPRINTS\Altium_Footprint_Lib.PcbLib; Height: 0.26MM; Library Path: Y:\MIS_DATABASE\Library\ALTIUM_TOOL\SCHEMATICS_PARTS\MS_DISCRETE_Library.schlib; Mfr_name: YAGEO AMERICA; Mfr_part_number: RC0201JR-070RL; Mistral Part No: 110010070067-R; Package: 0201; Part_type: RESISTORS\FIXED; Project: PB_BUGBASE; RoHS: RoHS; SIGNAL_MODEL: RESISTOR_RES0201_0-5_22E_1%_22E_1%; Temperature: -55°C+125°C; Tolerance: 5%; Voltage: NA; Wattage: 1/20W; Weight: 0.17mg; Datasheet: Y:\MIS_DATABASE\DATASHEETS\RESISTORS\RCXXXXL-SER_MAR18.PDF
TP119-TP121 = TESTPOINT: TESTPOINT 1.0MM DRILL PTH; Chkd/date: MAZHAR/271211; Crtd /date: SHREESHAIL/041005; Distributor_name: NA; Distributor_part_number: NA; Height: NA; Mfr_name: LOCAL; Mistral Part No: 130009030938; Package: THRU-HOLE; Project: HSE; Datasheet: NA
C2 C330 C340 = CAP: CAP CERAMIC 0.1uF 50V 10% X7R AUTO 0402; Automotive Alternate_mfr_name: TDK; Automotive Alternate_mfr_part_number: CGA2B3X7R1H104K050BB; Chkd/date: MANIRAJA/250221; Crtd /date: ALVY/240221; Custom_Duty: 15%; Customs_HS_Code: 85322990; Direct Alternate_mfr_name: TDK; Direct Alternate_mfr_part_number: C1005X7R1H104K050BE; Distributor_name: MOUSER; Distributor_part_number: 81-GRT155R71H104KE1D; Footprint Path: Y:\MIS_DATABASE\Library\ALTIUM_TOOL\PCB_FOOTPRINTS\Altium_Footprint_Lib.PcbLib; Height: 0.55MM; Library Path: Y:\MIS_DATABASE\Library\ALTIUM_TOOL\SCHEMATICS_PARTS\MS_DISCRETE_Library.schlib; Mfr_name: MURATA; Mfr_part_number: GRT155R71H104KE01D; Mistral Part No: 120019030005-R; Package: 0402; Part_type: CAPACITORS\CERAMIC; Project: TI_DRA821 SK EVM BRD; RoHS: RoHS; Temperature: -55°C+125°C; Tolerance: 10%; Voltage: 50V; Wattage: NA; Weight: NA; Datasheet: Y:\MIS_DATABASE\DATASHEETS\CAPACITORS\GRT155R71H104KE01.PDF
C11-C14 C335-C338 = CAP: CAP CERAMIC 22uF 16V 20% X5R 0603; Chkd/date: MANIRAJA/280917; Crtd /date: MANIRAJA/280917; Custom_Duty: 15%; Customs_HS_Code: 85322990; Distributor_name: DIGIKEY; Distributor_part_number: 1276-7076-1-ND; Footprint Path: Y:\MIS_DATABASE\Library\ALTIUM_TOOL\PCB_FOOTPRINTS\Altium_Footprint_Lib.PcbLib; Height: 0.80MM; Library Path: Y:\MIS_DATABASE\Library\ALTIUM_TOOL\SCHEMATICS_PARTS\MS_DISCRETE_Library.schlib; Mfr_name: SAMSUNG; Mfr_part_number: CL10A226MO7JZNC; Mistral Part No: 120017090007-R; Package: 0603; Part_type: CAPACITORS\CERAMIC; Project: TI_MAXIE_CPB; RoHS: RoHS; Temperature: -55°C+85°C; Tolerance: 20%; Voltage: 16V; Wattage: NA; Weight: 2mg; Datasheet: Y:\MIS_DATABASE\DATASHEETS\CAPACITORS\CL10A226MO7JZNC.PDF
C49 = CAP: CAP CERAMIC 0.1uF 50V 10% X7R AUTO 0402; Chkd/date: MANIRAJA/250221; Crtd /date: ALVY/240221; Custom_Duty: 15%; Customs_HS_Code: 85322990; Distributor_name: MOUSER; Distributor_part_number: 81-GRT155R71H104KE1D; Footprint Path: Y:\MIS_DATABASE\Library\ALTIUM_TOOL\PCB_FOOTPRINTS\Altium_Footprint_Lib.PcbLib; Height: 0.55MM; Library Path: Y:\MIS_DATABASE\Library\ALTIUM_TOOL\SCHEMATICS_PARTS\MS_DISCRETE_Library.schlib; Mfr_name: MURATA; Mfr_part_number: GRT155R71H104KE01D; Mistral Part No: 120019030005-R; Package: 0402; Part_type: CAPACITORS\CERAMIC; Project: TI_DRA821 SK EVM BRD; RoHS: RoHS; Temperature: -55°C+125°C; Tolerance: 10%; Voltage: 50V; Wattage: NA; Weight: NA; Datasheet: Y:\MIS_DATABASE\DATASHEETS\CAPACITORS\GRT155R71H104KE01.PDF
C52 C54 = CAP: CAP CERAMIC 2.2uF 10V 20% X5R 0201; Chkd/date: PRADEEP/130623; Crtd /date: PRADEEP/130623; Custom_Duty: 15%; Customs_HS_Code: 85322990; Distributor_name: NA; Distributor_part_number: NA; Footprint Path: Y:\MIS_DATABASE\Library\ALTIUM_TOOL\PCB_FOOTPRINTS\Altium_Footprint_Lib.PcbLib; Height: 0.55MM; Library Path: Y:\MIS_DATABASE\Library\ALTIUM_TOOL\SCHEMATICS_PARTS\MS_DISCRETE_Library.schlib; Mfr_name: MURATA; Mfr_part_number: GRM035R61A225ME01; Mistral Part No: 120022060026-R; Package: 0201; Part_type: CAPACITORS\CERAMIC; Project: AM62P_SK; RoHS: RoHS; Temperature: -55°C+85°C; Tolerance: 20%; Voltage: 10V; Wattage: NA; Weight: 0.57mg; Datasheet: Y:\MIS_DATABASE\DATASHEETS\CAPACITORS\GRM035R61A225ME01.PDF
C53 C60 C64 C74 C78 C86 C177 C178 = CAP: CAP CERAMIC 0.1uF 16V 10% X7S AUTO 0201; Chkd/date: MANIRAJA/110321; Crtd /date: ALVY/110321; Custom_Duty: 15%; Customs_HS_Code: 85322990; Distributor_name: DIGIKEY; Distributor_part_number: 490-GRT033C71C104KE01DTR-ND; Footprint Path: Y:\MIS_DATABASE\Library\ALTIUM_TOOL\PCB_FOOTPRINTS\Altium_Footprint_Lib.PcbLib; Height: 0.33MM; Library Path: Y:\MIS_DATABASE\Library\ALTIUM_TOOL\SCHEMATICS_PARTS\MS_DISCRETE_Library.schlib; Mfr_name: MURATA; Mfr_part_number: GRT033C71C104KE01D; Mistral Part No: 120021030007-R; Package: 0201; Part_type: CAPACITORS\CERAMIC; Project: J7ES_SK_BRD; RoHS: RoHS; Temperature: -55°C+125°C; Tolerance: 10%; Voltage: 16V; Wattage: NA; Weight: 330mg; Datasheet: Y:\MIS_DATABASE\DATASHEETS\CAPACITORS\GRT033C71C104KE01.PDF
C55 C65 C90 C130 C134 C135 C138 C142 C160 C167 C170 C171 C174 = CAP: CAP CERAMIC 1uF 10V 20% X6S 0201; Chkd/date: PRADEEP/130623; Crtd /date: PRADEEP/130623; Custom_Duty: 15%; Customs_HS_Code: 85322990; Distributor_name: DIGIKEY; Distributor_part_number: 490-GRT033C81A105ME13DTR-ND; Footprint Path: Y:\MIS_DATABASE\Library\ALTIUM_TOOL\PCB_FOOTPRINTS\Altium_Footprint_Lib.PcbLib; Height: 0.39MM; Library Path: Y:\MIS_DATABASE\Library\ALTIUM_TOOL\SCHEMATICS_PARTS\MS_DISCRETE_Library.schlib; Mfr_name: MURATA; Mfr_part_number: GRT033C81A105ME13D; Mistral Part No: 120022060020-R; Package: 0201; Part_type: CAPACITORS\CERAMIC; Project: AM62P_SK; RoHS: RoHS; Temperature: -55°C+105°C; Tolerance: 20%; Voltage: 10V; Wattage: NA; Weight: NA; Datasheet: Y:\MIS_DATABASE\DATASHEETS\CAPACITORS\GRT033C81A105ME13D.PDF
C71 C77 C368 = CAP: CAP CERAMIC 10uF 10V 20% X5R 0402; Chkd/date: PRADEEP/130623; Crtd /date: PRADEEP/130623; Custom_Duty: 15%; Customs_HS_Code: 85322990; Distributor_name: NA; Distributor_part_number: NA; Footprint Path: Y:\MIS_DATABASE\Library\ALTIUM_TOOL\PCB_FOOTPRINTS\Altium_Footprint_Lib.PcbLib; Height: 0.55MM; Library Path: Y:\MIS_DATABASE\Library\ALTIUM_TOOL\SCHEMATICS_PARTS\MS_DISCRETE_Library.schlib; Mfr_name: MURATA; Mfr_part_number: GRM155R61A106ME18; Mistral Part No: 120022060018-R; Package: 0402; Part_type: CAPACITORS\CERAMIC; Project: AM62P_SK; RoHS: RoHS; Temperature: -55°C+85°C; Tolerance: 20%; Voltage: 10V; Wattage: NA; Weight: 6mg; Datasheet: Y:\MIS_DATABASE\DATASHEETS\CAPACITORS\MURATA-GXX-SER_NOV17.PDF
C363 = CAP: CAP CERAMIC 1uF 25V 5% X7R 0805; Chkd/date: PRADEEP/150424; Crtd /date: SHANKARI/150424; Custom_Duty: 15%; Customs_HS_Code: 85423100; Distributor_name: DIGIKEY; Distributor_part_number: 478-KGM21AR71E105JUCT-ND; Footprint Path: Y:\MIS_DATABASE\Library\ALTIUM_TOOL\PCB_FOOTPRINTS\Altium_Footprint_Lib.PcbLib; Height: 1.45MM; Library Path: Y:\MIS_DATABASE\Library\ALTIUM_TOOL\SCHEMATICS_PARTS\MS_DISCRETE_Library.schlib; Mfr_name: AVX CORPORATION; Mfr_part_number: 08053C105JAT2A; Mistral Part No: 120024040007-R; Package: 0805; Part_type: CAPACITORS\CERAMIC; Project: AM62D_EVM; RoHS: RoHS; Temperature: -55°C+125°C; Tolerance: 5%; Voltage: 25V; Wattage: NA; Weight: 5.5mg; Datasheet: Y:\MIS_DATABASE\DATASHEETS\CAPACITORS\AVX_MLC.PDF
J1 = CON_AUDIOJACK6_STX-4235-3_3: CON AUDIO JACK DUAL 6POS 3.50MM FEMALE RT TH; Chkd/date: MANIRAJA/090818; Crtd /date: ALVY/080818; Custom_Duty: 24%; Customs_HS_Code: 85369090; Distributor_name: MOUSER; Distributor_part_number: 806-STX-4235-3/3-N; Footprint Path: Y:\MIS_DATABASE\Library\ALTIUM_TOOL\PCB_FOOTPRINTS\Altium_Footprint_Lib.PcbLib; Height: 26.00MM; Library Path: Y:\MIS_DATABASE\Library\ALTIUM_TOOL\SCHEMATICS_PARTS\MS_CONNECTOR_Library.schlib; Library Ref: CON_AUDIOJACK6_STX-4235-3/3; Mfr_name: KYCON; Mfr_part_number: STX-4235-3/3-N; Mistral Part No: 150018080005-R; Package: THRU-HOLE; Part_type: CONNECTOR\JACK; Project: TI_J7ES_EVM_FUSION2_SER_CAP; RoHS: RoHS; Temperature: -25°C+85°C; Tolerance: NA; Voltage: NA; Wattage: NA; Weight: NA; Datasheet: Y:\MIS_DATABASE\DATASHEETS\CONNECTORS\STX-4235-3-3-N.PDF
L2 = INDUCTOR: IND 2.2uH 20% 2.4A 0806; Chkd/date: PRADEEP/080124; Crtd /date: TAMILARASU/080124; Custom_Duty: 24%; Customs_HS_Code: 85437099; Distributor_name: DIGIKEY; Distributor_part_number: F10231CT-ND; Footprint Path: Y:\MIS_DATABASE\Library\ALTIUM_TOOL\PCB_FOOTPRINTS\Altium_Footprint_Lib.PcbLib; Height: 1.00MM; Library Path: Y:\MIS_DATABASE\Library\ALTIUM_TOOL\SCHEMATICS_PARTS\MS_FILTER_Library.schlib; Mfr_name: LITTELFUSE INC; Mfr_part_number: LPWI201610H2R2T; Mistral Part No: 130024010015-R; Package: 0806; Project: AM62D_EVM; RoHS: RoHS; Temperature: -40°C+85°C; Tolerance: 0.2; Voltage: NA; Wattage: NA; Weight: NA; Datasheet: Y:\MIS_DATABASE\DATASHEETS\DISCRETES\INDUCTORS\LPWI201610H2R2T.PDF
R3-R6 R409-R412 = RESISTOR: RES 4.3K 1/16W 5% 0402; Chkd/date: VASANTHA/190614; Crtd /date: NAVEED/160614; Custom_Duty: 15%; Customs_HS_Code: 85332119; Distributor_name: DIGIKEY; Distributor_part_number: RMCF0402JT4K30CT-ND; Footprint Path: Y:\MIS_DATABASE\Library\ALTIUM_TOOL\PCB_FOOTPRINTS\Altium_Footprint_Lib.PcbLib; Height: 0.40MM; Library Path: Y:\MIS_DATABASE\Library\ALTIUM_TOOL\SCHEMATICS_PARTS\MS_DISCRETE_Library.schlib; Mfr_name: STACKPOLE ELECTRONICS; Mfr_part_number: RMCF0402JT4K30; Mistral Part No: 110014060029-R; Package: 0402; Part_type: RESISTORS\FIXED; Project: AEGIS_POM; RoHS: RoHS; Temperature: -55°C+155°C; Tolerance: 5%; Voltage: NA; Wattage: 1/16W; Weight: 0.57mg; Datasheet: Y:\MIS_DATABASE\DATASHEETS\RESISTORS\RMCF-SER_JUL18.PDF
R60-R63 R161 = RESISTOR: RES 10K 1/20W 5% 0201; Chkd/date: MANIRAJA/050517; Crtd /date: MANIRAJA/050517; Custom_Duty: 15%; Customs_HS_Code: 85332119; Distributor_name: DIGIKEY; Distributor_part_number: 311-10KNCT-ND; Footprint Path: Y:\MIS_DATABASE\Library\ALTIUM_TOOL\PCB_FOOTPRINTS\Altium_Footprint_Lib.PcbLib; Height: 0.26MM; Library Path: Y:\MIS_DATABASE\Library\ALTIUM_TOOL\SCHEMATICS_PARTS\MS_DISCRETE_Library.schlib; Mfr_name: YAGEO AMERICA; Mfr_part_number: RC0201JR-0710KL; Mistral Part No: 110010070051-R; Package: 0201; Part_type: RESISTORS\FIXED; Project: GOLDEN-I LITE; RoHS: RoHS; Temperature: -55°C+125°C; Tolerance: 5%; Voltage: NA; Wattage: 1/20W; Weight: 0.17mg; Datasheet: Y:\MIS_DATABASE\DATASHEETS\RESISTORS\RCXXXXL-SER_MAR18.PDF
R413 R415 R416 = RESISTOR: RES 10K 1/16W 5% 0402; Chkd/date: VASANTHA/061216; Crtd /date: MAZHAR/230805; Custom_Duty: 15%; Customs_HS_Code: 85332119; Distributor_name: DIGIKEY; Distributor_part_number: 311-10KJRCT-ND; Footprint Path: Y:\MIS_DATABASE\Library\ALTIUM_TOOL\PCB_FOOTPRINTS\Altium_Footprint_Lib.PcbLib; Height: 0.40MM; Library Path: Y:\MIS_DATABASE\Library\ALTIUM_TOOL\SCHEMATICS_PARTS\MS_DISCRETE_Library.schlib; Mfr_name: YAGEO AMERICA; Mfr_part_number: RC0402JR-0710KL; Mistral Part No: 110011060021-R; Package: 0402; Part_type: RESISTORS\FIXED; Project: HSE; RoHS: RoHS; Temperature: -55°C+155°C; Tolerance: 5%; Voltage: NA; Wattage: 1/16W; Weight: 0.65mg; Datasheet: Y:\MIS_DATABASE\DATASHEETS\RESISTORS\RCXXXXL-SER_MAR18.PDF
TP25-TP27 TP31 = TESTPOINT: TESTPOINT CIR 30 SMD; Chkd/date: SHREESHAIL/171006; Crtd /date: MAZHAR/171006; Custom_Duty: NA; Customs_HS_Code: NA; Distributor_name: NA; Distributor_part_number: NA; Footprint Path: Y:\MIS_DATABASE\Library\ALTIUM_TOOL\PCB_FOOTPRINTS\Altium_Footprint_Lib.PcbLib; Height: NA; Library Path: Y:\MIS_DATABASE\Library\ALTIUM_TOOL\SCHEMATICS_PARTS\MS_DISCRETE_Library.schlib; MECHANICAL 3D STEP FILE: NA; Mfr_name: LOCAL; Mistral Part No: 130009030930; Package: SMD; Project: BT MODULE_CSRBC04; RoHS: NA; Temperature: NA; Tolerance: NA; Voltage: NA; Wattage: NA; Weight: NA; Datasheet: NA
U8 = PCM6240QRTVRQ1_WQFN32: IC AUTOMOTIVE 4-CHANNEL 768KHz AUDIO ADC WITH INTEGRATED MICROPHONE BIAS AND INPUT FAULT DIAGNOSTICS WQFN32; Chkd/date: PRADEEP/221123; Crtd /date: TAMILARASU/221123; Custom_Duty: 15%; Customs_HS_Code: 85423100; Distributor_name: DIGIKEY; Distributor_part_number: 296-PCM6240QRTVRQ1TR-ND; Height: 0.80MM; Mfr_name: TEXAS INSTRUMENTS; Mistral Part No: 140223110001-R; Package: WQFN32; Part_type: ICS\ATOD; Project: AM62D_EVM; RoHS: RoHS; Temperature: -40°C+125°C; Tolerance: NA; Voltage: NA; Wattage: NA; Weight: NA; Datasheet: Y:\MIS_DATABASE\DATASHEETS\ICS\ATOD_DTOA\PCM6240.PDF
U75 = SN74LVC1G08DBVRE4_SOT23-5: IC SINGLE 2-INPUT POSITIVE AND GATE SOT23-5; Automotive Alternate_mfr_name: TEXAS INSTRUMENTS; Automotive Alternate_mfr_part_number: SN74LVC1G08QDBVRQ1; Chkd/date: SUHAS/221010; Crtd /date: USMAN/151008; Custom_Duty: 15%; Customs_HS_Code: 85423100; Distributor_name: DIGIKEY; Distributor_part_number: SN74LVC1G08DBVRE4-ND; Height: 1.45MM; Mfr_name: TEXAS INSTRUMENTS; Mistral Part No: 141009060026-R; Part_type: ICS\DIGITAL\GATES; Project: KHAN_MAIN; RoHS: Sb/ Br FREE; Temperature: -40°C+85°C; Datasheet: Y:\MIS_DATABASE\DATASHEETS\ICS\DIGITAL\GATES\SN74LVC1G08.PDF
J13 = CON40X2_SAMTEC: CON RECP 40X2 0.80MM PITCH SMD; Chkd/date: SUHAS/ 180311; Crtd /date: MUDDU/210510; Custom_Duty: 24%; Customs_HS_Code: 85369090; Distributor_name: DIGIKEY; Distributor_part_number: SAM8124-ND; Height: 3.25MM; Mfr_name: SAMTEC; Mfr_part_number: QSE-040-01-L-D-A; Mistral Part No: 150010050008; Package: SMD; Part_type: CONNECTOR\RECEPTACLE; Project: L13xDC_IEB_PEB; Temperature: -55°C+125°C; Weight: NA; Datasheet: Y:\MIS_DATABASE\DATASHEETS\CONNECTORS\QSE3-040.PDF
U34 = TXS0104EPWR_TSSOP14: IC TRANSLATOR 4-BIT BIDIRECTIONAL VOLTAGE-LEVEL TSSOP14; Chkd/date: MANIRAJA/130617; Crtd /date: BAVISH/251110; Custom_Duty: 15%; Customs_HS_Code: 85423100; Distributor_name: DIGIKEY; Distributor_part_number: 296-20697-1-ND; Height: 1.20MM; Mfr_name: TEXAS INSTRUMENTS; Mistral Part No: 141010110011-R; Package: TSSOP14; Part_type: ICS\INTERFACE; Project: EM-FLS; RoHS: RoHS; Temperature: -40°C+85°C; Tolerance: NA; Voltage: NA; Wattage: NA; Weight: 57.2mg; Datasheet: Y:\MIS_DATABASE\DATASHEETS\ICS\INTERFACE\TXS0104EPW.PDF

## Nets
DGND: C2.2 C11.2 C13.2 C49.2 C52.2 C53.1 C54.2 C55.2 C60.1 C64.2 C65.2 C71.2 C74.2 C77.2 C78.2 C86.2 C90.2 C130.2 C134.2 C135.2 C138.2 C142.2 C160.2 C167.2 C170.2 C171.2 C174.2 C177.2 C178.2 C330.2 C336.2 C338.2 C340.2 C363.2 C368.2 J1.1A J1.1B J13.7 J13.8 J13.15 J13.16 J13.22 J13.25 J13.26 J13.31 J13.35 J13.36 J13.45 J13.46 J13.49 J13.50 J13.57 J13.58 J13.65 J13.66 J13.75 J13.76 J13.81(GND1) J13.82(GND2) J13.83(GND3) J13.84(GND4) J13.85(GND5) J13.86(GND6) J13.87(GND7) J13.88(GND8) R61.2 R63.2 R145.2 R146.2 R147.2 R148.2 R149.2 R150.2 R151.2 R152.2 R153.2 R154.2 R155.2 R156.2 R157.2 R158.2 R159.2 R160.2 R415.1 R553.2 R557.2 R564.2 TP121.1(TP) U8.8(AVSS) U8.33(VSS) U34.7(GND) U75.3(GND) ; also on sheet 1 2 3 4 10 12 13 14 16 17 18 19 20 21 22 31 32 33 34 35 36 37 38 39 40 41 42 43 44 45 46 47 48 49 50 51 52 53 54 55 56 57 58
VBAT_IN: C49.1 C55.1 U8.21(VBAT_IN) ; also on sheet 56
VCC1V8_SYS: C138.1 C142.1 C160.1 C167.1 C177.1 J13.10 J13.12 R161.2 R198.1 R200.1 R503.1 R508.1 U34.1(VCCA) ; also on sheet 1 2 4 10 20 21 22 33 37 38 39 42 43 49 50 52 53 54 55 56 57 58
VCC3V3_TA: R126.2 R127.2 R128.2 R129.2 R130.2 R131.2 R132.2 R133.2 R134.2 R135.2 R136.2 R137.2 R138.2 R139.2 R140.2 R141.2 ; also on sheet 3 43
VCC_1V8_IOVDD: C71.1 C74.1 C340.1 R60.1 R62.1 R413.2 R416.2 U8.27(IOVDD) U75.5(VCC) ; also on sheet 16 56
VCC_3V3_AVDD: C52.1 C53.2 C86.1 C90.1 L2.1 U8.1(AVDD) U8.3(BSTVDD) ; also on sheet 56
VCC_3V3_SYS: C178.1 U34.14(VCCB) ; also on sheet 1 2 3 10 14 17 18 19 20 22 31 33 37 38 40 41 42 45 46 48 49 50 51 52 53 54 55 56 57 58
VCC_5V0: C130.1 C134.1 C135.1 C170.1 C171.1 C174.1 J13.2 J13.4 J13.6 ; also on sheet 14 31 32 34 51 52 54
AUDIO_EXT_REFCLK0: R538.2 ; also on sheet 22
BOOTMODE0: RA2.2 ; also on sheet 43
BOOTMODE0_R: RA2.3 ; also on sheet 11
BOOTMODE1: RA7.1 ; also on sheet 43
BOOTMODE1_R: RA7.8 ; also on sheet 11
BOOTMODE2: RA7.2 ; also on sheet 43
BOOTMODE2_R: RA7.7 ; also on sheet 11
BOOTMODE3: RA7.3 ; also on sheet 43
BOOTMODE3_R: RA7.6 ; also on sheet 11
BOOTMODE4: RA7.4 ; also on sheet 43
BOOTMODE4_R: RA7.5 ; also on sheet 11
BOOTMODE5: RA5.1 ; also on sheet 43
BOOTMODE5_R: RA5.8 ; also on sheet 11
BOOTMODE6: RA6.2 ; also on sheet 43
BOOTMODE6_R: RA6.7 ; also on sheet 11
BOOTMODE7: RA1.2 ; also on sheet 43
BOOTMODE7_R: RA1.3 ; also on sheet 11
BOOTMODE8: RA2.1 ; also on sheet 43
BOOTMODE8_R: RA2.4 ; also on sheet 11
BOOTMODE9: RA6.4 ; also on sheet 43
BOOTMODE9_R: RA6.5 ; also on sheet 11
BOOTMODE10: RA6.3 ; also on sheet 43
BOOTMODE10_R: RA6.6 ; also on sheet 11
BOOTMODE11: RA1.1 ; also on sheet 43
BOOTMODE11_R: RA1.4 ; also on sheet 11
BOOTMODE12: RA5.3 ; also on sheet 43
BOOTMODE12_R: RA5.6 ; also on sheet 11
BOOTMODE13: RA5.4 ; also on sheet 43
BOOTMODE13_R: RA5.5 ; also on sheet 11
BOOTMODE14: RA6.1 ; also on sheet 43
BOOTMODE14_R: RA6.8 ; also on sheet 11
BOOTMODE15: RA5.2 ; also on sheet 43
BOOTMODE15_R: RA5.7 ; also on sheet 11
CP_GEMAC_CPTS0_HW1TSPUSH: U47.B15(SPI0_D0) ; also on sheet 20
CP_GEMAC_CPTS0_HW2TSPUSH: U47.E15(SPI0_D1) ; also on sheet 20
CP_GEMAC_CPTS0_TS_SYNC: R706.1 TP120.1(TP)
CPLD/EXP1_McASP0_ACLKR: R174.2 ; also on sheet 20 54
CPLD/EXP1_McASP0_AFSR: R189.2 ; also on sheet 20 54
CPLD/EXP1_McASP0_AFSX: R173.2 ; also on sheet 20 54
CPLD/EXP1_McASP0_AXR0: R188.2 ; also on sheet 20 54
CPLD/EXP2_McASP2_ACLKR: J13.43 ; also on sheet 11 16
CPLD/EXP2_McASP2_ACLKX: J13.37 ; also on sheet 11 22
CPLD/EXP2_McASP2_AFSR: J13.41 ; also on sheet 11 20
CPLD/EXP2_McASP2_AFSX: J13.39 ; also on sheet 11 20
CPLD/EXP2_McASP2_AXR0: J13.27 ; also on sheet 11 22
CPLD/EXP2_McASP2_AXR1: J13.29 ; also on sheet 11 22
CPLD/EXP2_McASP2_AXR3: J13.28 ; also on sheet 11 22
CPLD/EXP2_McASP2_AXR4: J13.30 ; also on sheet 11 22
CPLD/EXP2_McASP2_AXR14: J13.70 ; also on sheet 11 16
CPLD/EXP2_McASP2_AXR15: J13.72 ; also on sheet 11 16
CPLD_ECAP0_APWM_OUT: U47.C16(SPI0_CS1) ; also on sheet 20
CPLD_ECAP1_APWM_OUT: U47.E14(UART0_RXD) ; also on sheet 20
CPLD_ECAP2_APWM_OUT: U47.D15(UART0_TXD) ; also on sheet 20
CPLD_OBSCLK1: R204.2 ; also on sheet 22
EXP1_McASP0_ACLKX: R172.2 ; also on sheet 1 54
EXP1_McASP0_AXR1: R186.2 ; also on sheet 1 54
EXP1_McASP0_AXR2: R187.2 ; also on sheet 54
EXP1_McASP0_AXR3: R171.2 ; also on sheet 54
EXP2_CLK_IN: J13.33 ; also on sheet 22
EXP2_CLK_OUT: J13.47 ; also on sheet 22
EXP2_EHRPWM0_A: J13.3 U47.D16(SPI0_CS0)
EXP2_EHRPWM1_A: J13.5 R705.1
EXP2_GPIO0_45: J13.42 U47.U22(GPIO0_45)
EXP2_GPIO0_46: J13.44 U47.U21(GPIO0_46)
EXP2_GPIO0_47: J13.51 U47.U20(GPIO0_47)
EXP2_GPIO0_48: J13.53 U47.U19(GPIO0_48)
EXP2_GPIO0_55: J13.77 U47.W22(GPIO0_55)
EXP2_GPIO0_56: J13.79 U47.W21(GPIO0_56)
EXP2_GPIO0_57: J13.78 U47.W20(GPIO0_57)
EXP2_GPIO0_58: J13.80 U47.W19(GPIO0_58)
EXP2_McASP2_AXR5: J13.32 ; also on sheet 11
EXP2_McASP2_AXR6: J13.34 ; also on sheet 11
EXP2_McASP2_AXR7: J13.38 ; also on sheet 11
EXP2_McASP2_AXR8: J13.40 ; also on sheet 11
EXP2_McASP2_AXR9: J13.67 ; also on sheet 11
EXP2_McASP2_AXR10: J13.69 ; also on sheet 11
EXP2_McASP2_AXR11: J13.71 ; also on sheet 11
EXP2_McASP2_AXR12: J13.73 ; also on sheet 11
EXP2_McASP2_AXR13: J13.68 ; also on sheet 11
EXP2_MCU_SPI1_CS2_1V8: J13.24 ; also on sheet 54
EXP2_TIMESTAMP0_IN: J13.9 ; also on sheet 20
EXP2_TIMESTAMP1_IN: J13.11 ; also on sheet 20
EXT_CLKOUT0: R170.1 ; also on sheet 48
EXT_CLKOUT0_R: R170.2 R175.2 R692.2 R704.1 U47.B16(EXT_REFCLK1)
EXT_REFCLK1: R175.1 ; also on sheet 22
GPIO1_23_INTn_1V8: U47.Y22(GPIO0_60) ; also on sheet 55
GPIO_PCM2_RST: R414.1 ; also on sheet 55
I2C0_SCL_R: R195.1 R200.2 R204.1 U47.D17(I2C0_SCL)
MCAN0_RX: U47.C18(MCAN0_RX) ; also on sheet 58
MCAN0_TX: U47.B17(MCAN0_TX) ; also on sheet 58
MCU_SPI1_CLK: U34.13(B1) ; also on sheet 48
MCU_SPI1_CLK_1V8: J13.17 U34.2(A1)
MCU_SPI1_CS0: U34.12(B2) ; also on sheet 48
MCU_SPI1_CS0_1V8: J13.23 U34.3(A2)
MCU_SPI1_D0: U34.11(B3) ; also on sheet 48
MCU_SPI1_D0_1V8: J13.19 U34.4(A3)
MCU_SPI1_D1: U34.10(B4) ; also on sheet 48
MCU_SPI1_D1_1V8: J13.21 U34.5(A4)
MIC2_BIAS: C2.1 C330.1 C363.1 R3.1 R4.1 R5.1 R6.1 R409.1 R410.1 R411.1 R412.1 U8.6(MICBIAS)
PCM1_GPIO1: R432.1 ; also on sheet 56
PCM2_ADDR_0: R62.2 R63.1 U8.24(ADDR0_SCLK)
PCM2_ADDR_1: R60.2 R61.1 U8.23(ADDR1_MISO)
PCM2_AREG: C64.1 C368.1 U8.2(AREG)
PCM2_BSTOUT: C54.1 C60.2 U8.5(BSTOUT)
PCM2_IN1N: C13.1 R5.2 U8.10(IN1M)
PCM2_IN1P: C14.1 R6.2 U8.9(IN1P)
PCM2_IN2N: C11.1 R3.2 U8.12(IN2M)
PCM2_IN2P: C12.1 R4.2 U8.11(IN2P)
PCM2_IN3N: C338.1 R412.2 U8.14(IN3M)
PCM2_IN3P: C337.1 R411.2 U8.13(IN3P)
PCM2_IN4N: C336.1 R410.2 U8.16(IN4M)
PCM2_IN4P: C335.1 R409.2 U8.15(IN4P)
PCM2_INT_1V8: R46.1 ; also on sheet 55
PCM2_McASP2_AXR14: R431.2 R433.1
PCM2_RESETn: R415.2 R416.1 U8.22(SHDNZ) U75.4(Y)
PCM2_VREF: C65.1 U8.7(VREF)
PCM6240_McASP2_ACLKR: U8.30(BCLK) ; also on sheet 16 56
PCM6240_McASP2_AFSR: U8.31(FSYNC) ; also on sheet 20 56
PCM6240_McASP2_AXR14: R431.1 ; also on sheet 16 56
PCM6240_McASP2_AXR15: R435.1 ; also on sheet 16
PORz_OUT_1V8: J13.1 ; also on sheet 10 54
RESETSTATz: U75.2(B) ; also on sheet 10 37 38 39 40 41 43 49 55 56
SoC_EMU0: U47.C13(EMU0) ; also on sheet 45 46
SoC_EMU1: U47.E10(EMU1) ; also on sheet 45 46
SoC_I2C0_SCL_1V8: R195.2 U8.25(SCL_MOSI) ; also on sheet 1 21 49 50 53 56
SoC_I2C0_SDA_1V8: R514.2 U8.26(SDA_SSZ) ; also on sheet 1 21 49 50 53 56
SoC_I2C1_SCL: J13.18 R503.2 U47.C17(I2C1_SCL)
SoC_I2C1_SDA: J13.20 R198.2 U47.E17(I2C1_SDA)
SoC_TCK: U47.A14(TCK) ; also on sheet 45 46
SoC_TDI: U47.A16(TDI) ; also on sheet 45 46
SoC_TDO: R542.1 ; also on sheet 45 46
SoC_TMS: U47.B14(TMS) ; also on sheet 45 46
SoC_TRST#: R564.1 U47.F15(TRSTN) ; also on sheet 45 46
SoC_USB0_DM: U47.AA10(USB0_DM) ; also on sheet 52
SoC_USB0_DP: U47.AA9(USB0_DP) ; also on sheet 52
SoC_USB0_DRVVBUS: U47.C20(USB0_DRVVBUS) ; also on sheet 52
SoC_USB0_RCALIB: R553.1 U47.W10(USB0_RCALIB)
SoC_USB0_VBUS: U47.V8(USB0_VBUS) ; also on sheet 52
SoC_USB1_DM: U47.Y11(USB1_DM) ; also on sheet 51
SoC_USB1_DP: U47.Y10(USB1_DP) ; also on sheet 51
SoC_USB1_DRVVBUS: U47.D19(USB1_DRVVBUS) ; also on sheet 52
SoC_USB1_RCALIB: R557.1 U47.U7(USB1_RCALIB)
SoC_USB1_VBUS: U47.V6(USB1_VBUS) ; also on sheet 51
SYNC1_OUT: R692.1 ; also on sheet 42
SYNC1_OUT1: R704.2 TP119.1(TP)
SYS_BOOTMODE0: R153.1 SW2.1 ; also on sheet 43
SYS_BOOTMODE1: R154.1 SW2.2 ; also on sheet 43
SYS_BOOTMODE2: R155.1 SW2.3 ; also on sheet 43
SYS_BOOTMODE3: R156.1 SW2.4 ; also on sheet 43
SYS_BOOTMODE4: R157.1 SW2.5 ; also on sheet 43
SYS_BOOTMODE5: R158.1 SW2.6 ; also on sheet 43
SYS_BOOTMODE6: R159.1 SW2.7 ; also on sheet 43
SYS_BOOTMODE7: R160.1 SW2.8 ; also on sheet 43
SYS_BOOTMODE8: R145.1 SW1.1 ; also on sheet 43
SYS_BOOTMODE9: R146.1 SW1.2 ; also on sheet 43
SYS_BOOTMODE10: R147.1 SW1.3 ; also on sheet 43
SYS_BOOTMODE11: R148.1 SW1.4 ; also on sheet 43
SYS_BOOTMODE12: R149.1 SW1.5 ; also on sheet 43
SYS_BOOTMODE13: R150.1 SW1.6 ; also on sheet 43
SYS_BOOTMODE14: R151.1 SW1.7 ; also on sheet 43
SYS_BOOTMODE15: R152.1 SW1.8 ; also on sheet 43
TIMER_IO7: J13.52 U47.C15(UART0_RTSN)
UART4_RXD: U47.T19(GPIO0_49) ; also on sheet 4
UART4_TXD: U47.U18(GPIO0_50) ; also on sheet 4
UART5_RXD: U47.V22(GPIO0_51) ; also on sheet 54
UART5_TXD: U47.V21(GPIO0_52) ; also on sheet 54
UART6_RXD: J13.62 U47.V19(GPIO0_53)
UART6_TXD: J13.60 U47.V18(GPIO0_54)
VSEL_SD_SOC_1V8: U47.Y21(GPIO0_59) ; also on sheet 55
N27132714: R137.1 SW2.13
N27132716: R136.1 SW2.14
N27132718: R135.1 SW2.15
N27132720: R134.1 SW2.16
N27132816: R131.1 SW1.11
N27132818: R130.1 SW1.12
N27132820: R129.1 SW1.13
N27132822: R128.1 SW1.14
N27132824: R133.1 SW1.9
N27132826: R132.1 SW1.10
N27132828: R127.1 SW1.15
N27132836: R126.1 SW1.16
N27133243: R141.1 SW2.9
N27133247: R140.1 SW2.10
N27133249: R139.1 SW2.11
N27133251: R138.1 SW2.12
N27153825: R188.1 U47.B20(MCASP0_AXR0)
N27153827: R186.1 U47.B18(MCASP0_AXR1)
N27153829: R187.1 U47.B19(MCASP0_AXR2)
N27153831: R171.1 U47.C19(MCASP0_AXR3)
N27153833: R189.1 U47.B21(MCASP0_AFSR)
N27153850: R173.1 U47.A20(MCASP0_AFSX)
N27153866: R172.1 U47.A19(MCASP0_ACLKX)
N27153868: R174.1 U47.A21(MCASP0_ACLKR)
N27154979: R542.2 U47.C14(TDO)
N27158706: R508.2 R514.1 U47.E16(I2C0_SDA)
N27158712: R538.1 U47.F14(UART0_CTSN)
N27158890: R705.2 R706.2 U47.A17(SPI0_CLK)
N27212579: R161.1 U34.8(OE)
N27224404: R432.2 R433.2 R435.2 U8.29(SDOUT)
N27224468: C337.2 J1.5B
N27224561: L2.2 U8.4(BSTSW)
N27224667: C335.2 J1.2B
N27224751: TP27.1(TP) U8.18(GPIO3)
N27224753: TP31.1(TP) U8.20(GPIO2)
N27224897: C14.2 J1.5A
N27225024: C77.1 C78.1 U8.32(DREG)
N27225078: C12.2 J1.2A
N27225127: TP26.1(TP) U8.19(GPI1)
N27225129: TP25.1(TP) U8.17(GPI2)
N27225150: R46.2 U8.28(GPIO1)
N27226002: R413.1 R414.2 U75.1(A)

Not connected (* = marked no-connect by the designer): J13 13* 14* 48* 54* 55* 56* 59* 61* 63* 64* 74*; U34 6(NC1)* 9(NC2)*; U47 AA12(CSI0_RXP2)* AA13(CSI0_RXN2)* AA22(GPIO0_64)* AB10(CSI0_RXP3)* AB11(CSI0_RXN3)* AB13(CSI0_RXCLKP)* AB14(CSI0_RXCLKN)* C6(RSVD0)* D6(RSVD1)* E7(RSVD2)* T18(GPIO0_61)* U11(RSVD6)* U17(GPIO0_62)* V10(CSI0_RXRCALIB)* V11(RSVD7)* V17(GPIO0_63)* W12(CSI0_RXN0)* W13(CSI0_RXP0)* Y13(CSI0_RXN1)* Y14(CSI0_RXP1)*

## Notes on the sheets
sheet 5
- AUDIO - MICROPHONE/LINE IN 2
- I2C ADDRESS: 0X49
- CAD Note: Resistors R433, R432 & R435
  shall share same pad
- PCM2 RESET
- ADC Supply & Decaps
- CAD Note: Place these decaps near the IOVDD supply pin
- I2C address selection
          device 2
- CAD Note: Place these decaps near the AVDD supply pin
sheet 6
- AUDIO EXPANSION CONNECTOR #2
- AUDIO EXPANSION DECAPS
- AEC2  LEVEL TRANSLATOR
sheet 7
- SOC - MCASP
- SOC - JTAG
- SOC -  UART , GPIOs
- SOC - GENERAL
- RESERVED PINS
- CAD-NOTE: QUADPAD R175, R170 , R692  and R704
sheet 8
- SOC - USB
- 90E
- To Type- C connector
- 90E
- To Type- A connector
- SOC CSI UNUSED
sheet 9
- BOOT MODE SWITCHES
- D-Note: VCC3V3_TA supply is used for test automation.
  Connect SoC_DVDD3V3 in the custom board design when buffers are not used
- BOOT MODES SUPPORTED
- SWITCH ON  =  LOGIC 1
  SWITCH OFF =  LOGIC 0
- 1. OSPI
- 2. MMC1 - SD CARD
- Silk: BMODE 0-7
- Silk: BMODE 8-15
- 3. UART
- 4. eMMC
- 5. ETHERNET
- 6. USB0 DFU
- 7. USB0 MS
- BOOTMODE PINS
- Signals from Bootmode buffer
- D-NOTE:
  1. 1K Resistor at the output of the buffer is
  recommended when the bootmode pins are used for
  alternate functions
  2. Replace 1K Resistor at the output of the buffer with
  resistor of value 0E when bootmode buffers are not used
- D-Note :
  Connect SYS_BOOTMODE signals when
  bootmode buffers are not used
